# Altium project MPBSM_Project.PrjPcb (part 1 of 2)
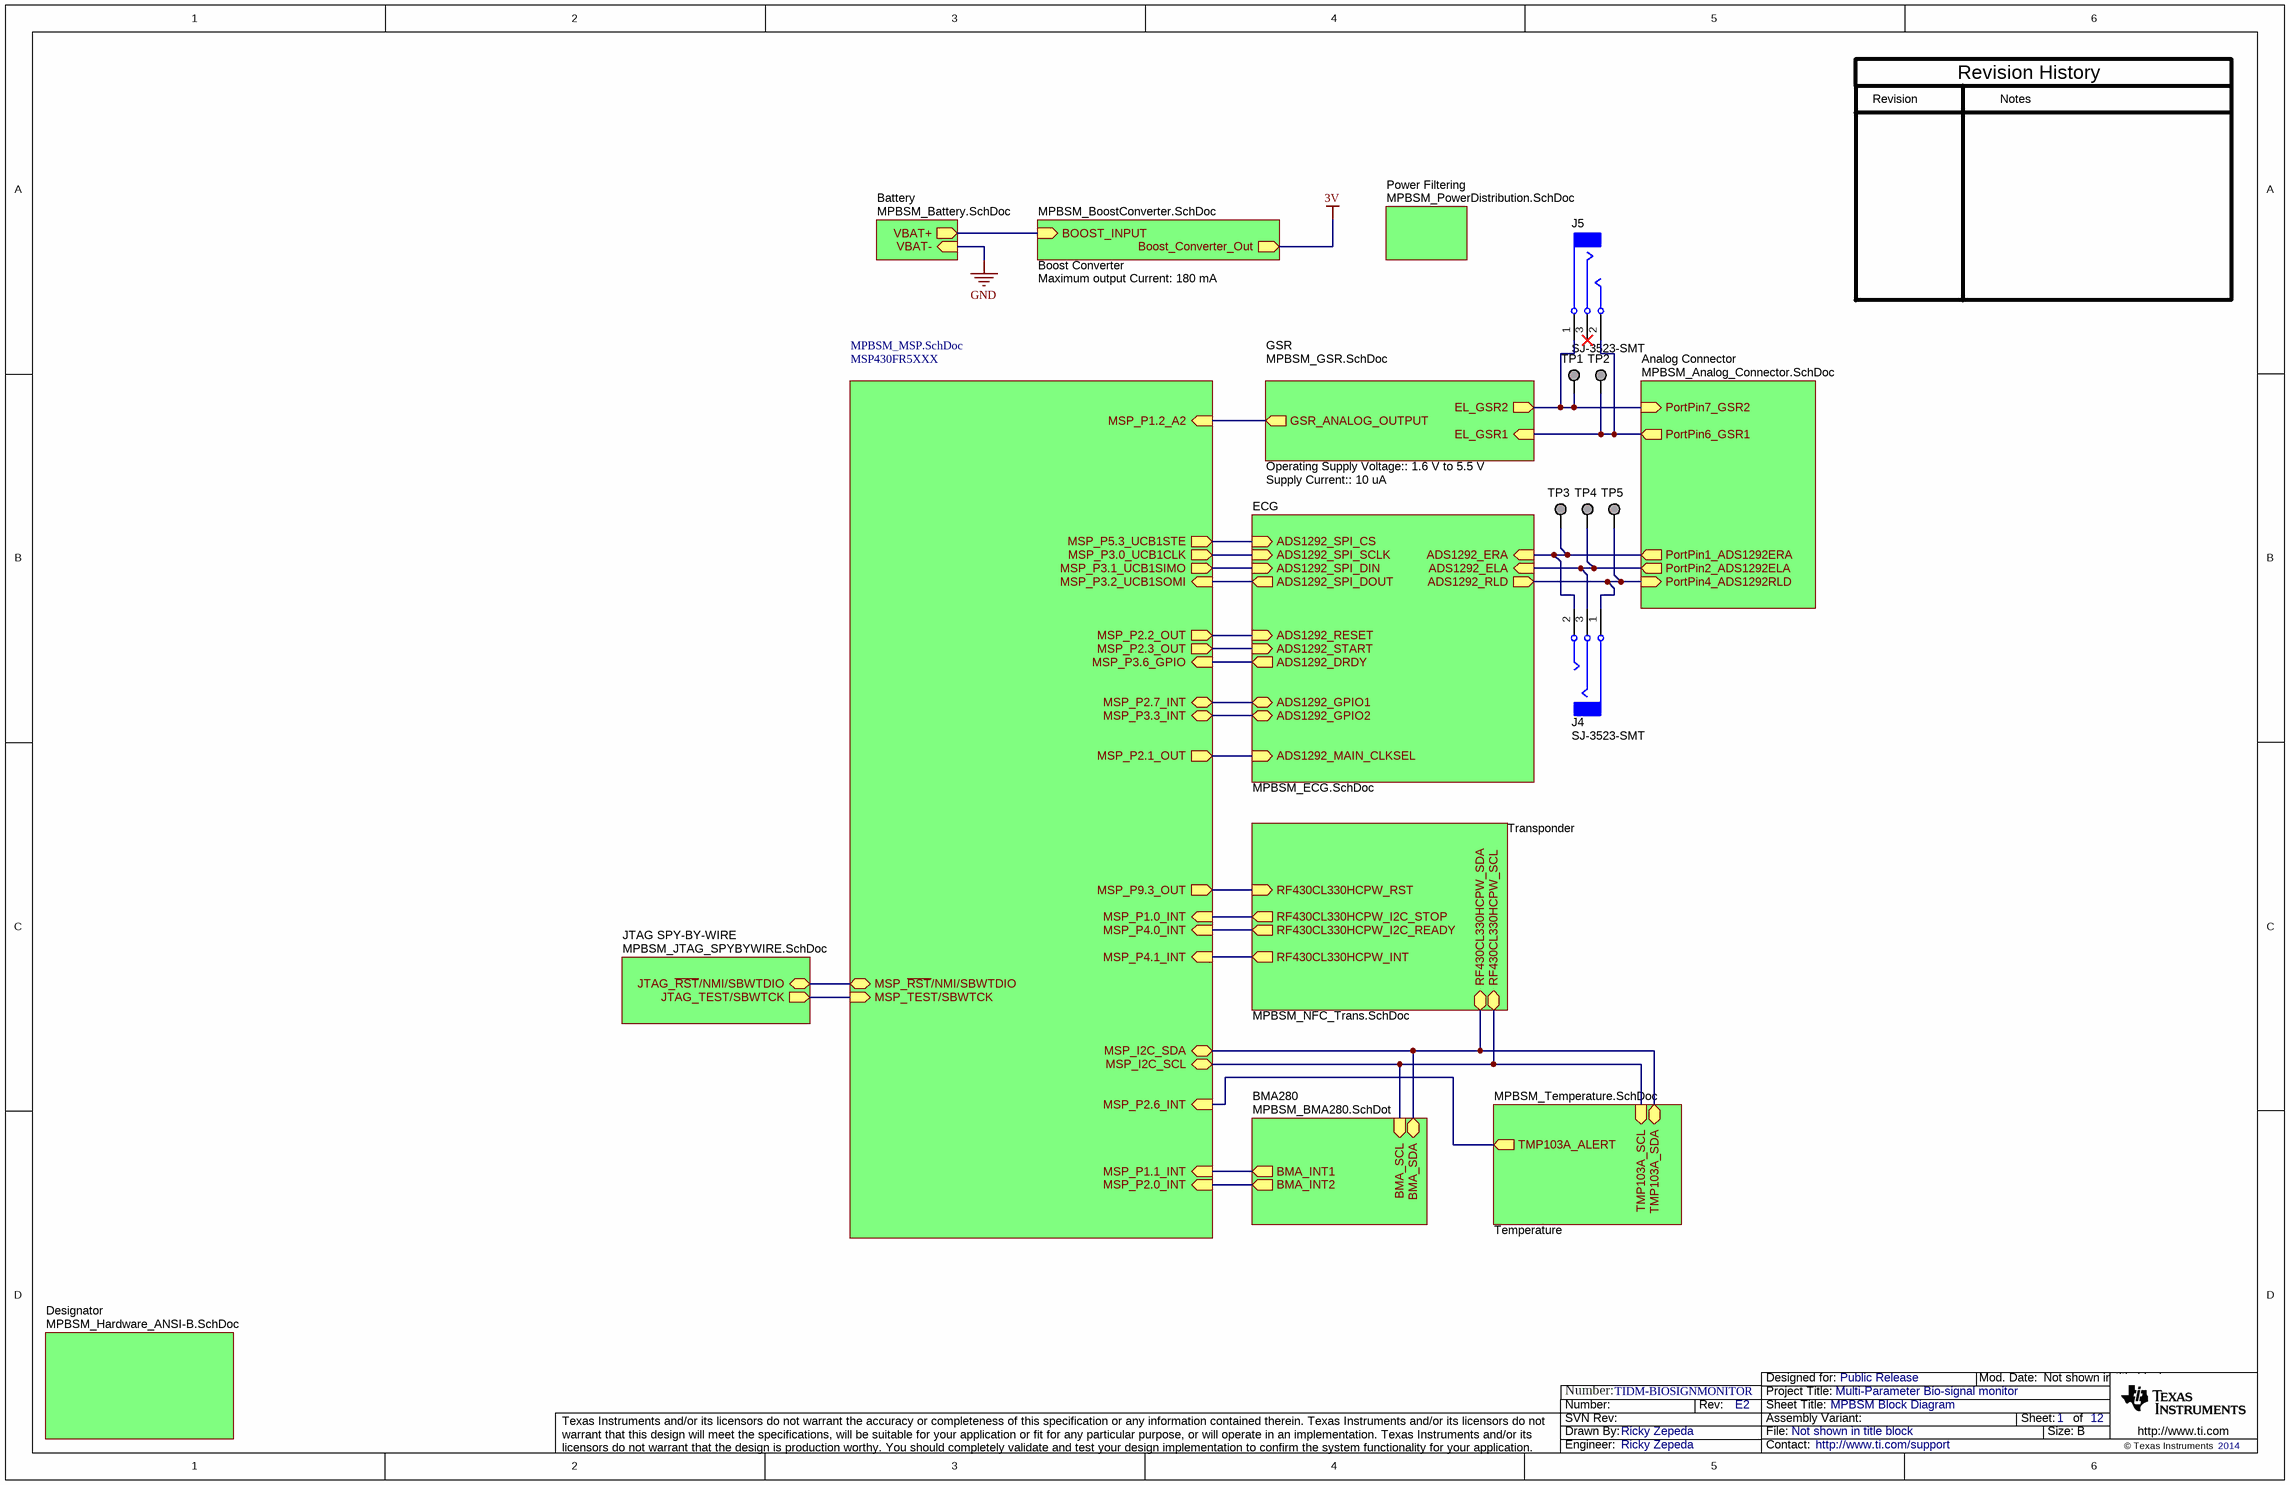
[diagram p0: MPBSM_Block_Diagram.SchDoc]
CopyrightYear: 2014; PCB_Layout: Ricardo Zepeda; PCB_Rev: 002; PRJ_Customer: Public Release; PRJ_Engineer: Ricky Zepeda; PRJ_Title: Multi-Parameter Bio-signal monitor; SCH_Rev: E2; TechSupport: http://www.ti.com/support
12 sheets, 158 parts. Net scope: hierarchical (ports join the sheet entries above them; power ports are global).
Board files: MPBSMLayoutvOverlay.PcbDoc, MPBSMLayoutvFR4.PcbDoc
Sheets:
  MPBSM_Block_Diagram.SchDoc
    MSP430FR5XXX = MPBSM_MSP.SchDoc
    Designator = MPBSM_Hardware_ANSI-B.SchDoc
    JTAG SPY-BY-WIRE = MPBSM_JTAG_SPYBYWIRE.SchDoc
    GSR = MPBSM_GSR.SchDoc
    Battery = MPBSM_Battery.SchDoc
    Boost Converter = MPBSM_BoostConverter.SchDoc
    Transponder = MPBSM_NFC_Trans.SchDoc
    Temperature = MPBSM_Temperature.SchDoc
    ECG = MPBSM_ECG.SchDoc
    Power Filtering = MPBSM_PowerDistribution.SchDoc
    Analog Connector = MPBSM_Analog_Connector.SchDoc

## Sheet MPBSM_Block_Diagram.SchDoc: MPBSM Block Diagram
size 431 x 279 mm; Date: Not shown in title block; ApprovedBy: Not shown in title block; CheckedBy: Not shown in title block; Author: Not shown in title block; CompanyName: Not shown in title block; DrawnBy: Ricky Zepeda; Engineer: Not shown in title block; Organization: Not shown in title block; Address1: Not shown in title block; Address2: Not shown in title block; Address3: Not shown in title block; Address4: Not shown in title block; DocumentNumber: 1; Revision: Use project parameter SCH_Rev; SheetNumber: 1; SheetTotal: 12; PageSetup: Record=PageOptions¦CenterHorizontal=True¦CenterVertical=True¦PrintScale=1.00¦XCorrection=1.00¦YCorrection=1.00¦PrintKind=0¦BorderSize=5000000¦LeftOffset=0¦BottomOffset=0¦Orientation=2¦PaperLength=1000¦PaperWidth=1000¦Scale=100¦PaperSource=15¦PrintQuality=600¦MediaType=1¦DitherType=10¦PaperKind=Letter¦PrintScaleMode=1

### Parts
J4  SJ-3523-SMT  [CUI_SJ-3523-SMT]
J5  SJ-3523-SMT  [CUI_SJ-3523-SMT]
TP1  TESTPOINT  [TP_SM_1MM]  (value not drawn)  (no BOM)
TP2  TESTPOINT  [TP_SM_1MM]  (value not drawn)  (no BOM)
TP3  TESTPOINT  [TP_SM_1MM]  (value not drawn)  (no BOM)
TP4  TESTPOINT  [TP_SM_1MM]  (value not drawn)  (no BOM)
TP5  TESTPOINT  [TP_SM_1MM]  (value not drawn)  (no BOM)

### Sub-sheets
Analog Connector = MPBSM_Analog_Connector.SchDoc: PortPin7_GSR2 (in), PortPin6_GSR1 (out), PortPin2_ADS1292ELA (out), PortPin4_ADS1292RLD (in), PortPin1_ADS1292ERA (out)
Battery = MPBSM_Battery.SchDoc: VBAT- (in), VBAT+ (out)
BMA280 = MPBSM_BMA280.SchDot (file not in this document): BMA_INT1 (out), BMA_INT2 (out), BMA_SDA (bidir), BMA_SCL (in)
Boost Converter = MPBSM_BoostConverter.SchDoc: BOOST_INPUT (in), Boost_Converter_Out (out)  | Maximum output Current: 180 mA
Designator = MPBSM_Hardware_ANSI-B.SchDoc: no entries
ECG = MPBSM_ECG.SchDoc: ADS1292_START (in), ADS1292_RESET (in), ADS1292_DRDY (out), ADS1292_SPI_CS (in), ADS1292_SPI_DIN (in), ADS1292_SPI_SCLK (in), ADS1292_SPI_DOUT (out), ADS1292_MAIN_CLKSEL (in), ADS1292_ERA (in), ADS1292_ELA (in), ADS1292_GPIO1 (bidir), ADS1292_GPIO2 (bidir), ADS1292_RLD (out)
GSR = MPBSM_GSR.SchDoc: GSR_ANALOG_OUTPUT (out), EL_GSR2 (out), EL_GSR1 (in)  | Operating Supply Voltage:: 1.6 V to 5.5 V; Supply Current:: 10 uA
JTAG SPY-BY-WIRE = MPBSM_JTAG_SPYBYWIRE.SchDoc: JTAG_~{RST}/NMI/SBWTDIO (bidir), JTAG_TEST/SBWTCK (out)
MSP430FR5XXX = MPBSM_MSP.SchDoc: MSP_TEST/SBWTCK (in), MSP_~{RST}/NMI/SBWTDIO (bidir), MSP_I2C_SDA (bidir), MSP_I2C_SCL (bidir), MSP_P1.2_A2 (in), MSP_P2.0_INT (in), MSP_P4.0_INT (in), MSP_P4.1_INT (in), MSP_P2.7_INT (bidir), MSP_P9.3_OUT (out), MSP_P2.2_OUT (out), MSP_P2.3_OUT (out), MSP_P1.0_INT (in), MSP_P2.1_OUT (out), MSP_P3.0_UCB1CLK (out), MSP_P3.3_INT (bidir), MSP_P3.2_UCB1SOMI (in), MSP_P3.6_GPIO (in), MSP_P1.1_INT (in), MSP_P5.3_UCB1STE (out), MSP_P3.1_UCB1SIMO (out), MSP_P2.6_INT (in)
Power Filtering = MPBSM_PowerDistribution.SchDoc: no entries
Temperature = MPBSM_Temperature.SchDoc: TMP103A_SCL (in), TMP103A_SDA (bidir), TMP103A_ALERT (out)
Transponder = MPBSM_NFC_Trans.SchDoc: RF430CL330HCPW_RST (in), RF430CL330HCPW_SCL (bidir), RF430CL330HCPW_SDA (bidir), RF430CL330HCPW_I2C_STOP (out), RF430CL330HCPW_I2C_READY (out), RF430CL330HCPW_INT (out)

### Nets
ADS1292_DRDY: sheet MSP430FR5XXX/MSP_P3.6_GPIO, sheet ECG/ADS1292_DRDY
ADS1292_ELA: J4.3(RING) TP4.1 ; sheet ECG/ADS1292_ELA, sheet Analog Connector/PortPin2_ADS1292ELA
ADS1292_ERA: J4.2(TIP) TP3.1 ; sheet ECG/ADS1292_ERA, sheet Analog Connector/PortPin1_ADS1292ERA
ADS1292_GPIO1: sheet MSP430FR5XXX/MSP_P2.7_INT, sheet ECG/ADS1292_GPIO1
ADS1292_GPIO2: sheet MSP430FR5XXX/MSP_P3.3_INT, sheet ECG/ADS1292_GPIO2
ADS1292_MAIN_CLKSEL: sheet MSP430FR5XXX/MSP_P2.1_OUT, sheet ECG/ADS1292_MAIN_CLKSEL
ADS1292_RESET: sheet MSP430FR5XXX/MSP_P2.2_OUT, sheet ECG/ADS1292_RESET
ADS1292_RLD: J4.1(SLEEVE) TP5.1 ; sheet ECG/ADS1292_RLD, sheet Analog Connector/PortPin4_ADS1292RLD
ADS1292_SPI_CS: sheet MSP430FR5XXX/MSP_P5.3_UCB1STE, sheet ECG/ADS1292_SPI_CS
ADS1292_SPI_DIN: sheet MSP430FR5XXX/MSP_P3.1_UCB1SIMO, sheet ECG/ADS1292_SPI_DIN
ADS1292_SPI_DOUT: sheet MSP430FR5XXX/MSP_P3.2_UCB1SOMI, sheet ECG/ADS1292_SPI_DOUT
ADS1292_SPI_SCLK: sheet MSP430FR5XXX/MSP_P3.0_UCB1CLK, sheet ECG/ADS1292_SPI_SCLK
ADS1292_START: sheet MSP430FR5XXX/MSP_P2.3_OUT, sheet ECG/ADS1292_START
BOOST_INPUT: sheet Battery/VBAT+, sheet Boost Converter/BOOST_INPUT
EL_GSR1: J5.2(TIP) TP2.1 ; sheet GSR/EL_GSR1, sheet Analog Connector/PortPin6_GSR1
EL_GSR2: J5.1(SLEEVE) TP1.1 ; sheet GSR/EL_GSR2, sheet Analog Connector/PortPin7_GSR2
GSR_ANALOG_OUTPUT: sheet MSP430FR5XXX/MSP_P1.2_A2, sheet GSR/GSR_ANALOG_OUTPUT
JTAG_TDO/TDI: sheet MSP430FR5XXX/MSP_~{RST}/NMI/SBWTDIO, sheet JTAG SPY-BY-WIRE/JTAG_~{RST}/NMI/SBWTDIO
JTAG_TEST/SBWTCK: sheet MSP430FR5XXX/MSP_TEST/SBWTCK, sheet JTAG SPY-BY-WIRE/JTAG_TEST/SBWTCK
MSP_P1.0_INT: sheet MSP430FR5XXX/MSP_P1.0_INT, sheet Transponder/RF430CL330HCPW_I2C_STOP
MSP_P1.1_INT: sheet MSP430FR5XXX/MSP_P1.1_INT, sheet BMA280/BMA_INT1
MSP_P2.0_INT: sheet MSP430FR5XXX/MSP_P2.0_INT, sheet BMA280/BMA_INT2
MSP_P2.6_INT: sheet MSP430FR5XXX/MSP_P2.6_INT, sheet Temperature/TMP103A_ALERT
MSP_P4.0_INT: sheet MSP430FR5XXX/MSP_P4.0_INT, sheet Transponder/RF430CL330HCPW_I2C_READY
MSP_P4.1_INT: sheet MSP430FR5XXX/MSP_P4.1_INT, sheet Transponder/RF430CL330HCPW_INT
MSP_P9.3_OUT: sheet MSP430FR5XXX/MSP_P9.3_OUT, sheet Transponder/RF430CL330HCPW_RST
MSP_UCB0SCL_TMP103_SCL_RF430CL330HCPW_SCL: sheet MSP430FR5XXX/MSP_I2C_SCL, sheet Transponder/RF430CL330HCPW_SCL, sheet BMA280/BMA_SCL, sheet Temperature/TMP103A_SCL
MSP_UCB0SDA_TMP103_SDA_RF430CL330HCPW_SDA: sheet MSP430FR5XXX/MSP_I2C_SDA, sheet Transponder/RF430CL330HCPW_SDA, sheet BMA280/BMA_SDA, sheet Temperature/TMP103A_SDA

Not connected (* = marked no-connect by the designer): J5 3(RING)*

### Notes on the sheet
- Revision
- Notes
- Revision History
- Number:
- TIDM-BIOSIGNMONITOR

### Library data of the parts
J4 J5 = SJ-3523-SMT: Audio Jack, 3.5mm, Stereo, R/A, SMT; Manufacturer: CUI Inc.; SymbolCreator: a0412235
TP1-TP5 = TP_SM_1MM: 1mm Test Point, SMT; Manufacturer: Any

## Sheet MPBSM_MSP.SchDoc: MPBSM MSP4305889 MCU
size 431 x 279 mm; Date: Not shown in title block; ApprovedBy: Not shown in title block; CheckedBy: Not shown in title block; Author: Not shown in title block; CompanyName: Not shown in title block; Engineer: Not shown in title block; Organization: Not shown in title block; Address1: Not shown in title block; Address2: Not shown in title block; Address3: Not shown in title block; Address4: Not shown in title block; DocumentNumber: 6; Revision: Use project parameter SCH_Rev; SheetNumber: 6; SheetTotal: 12; PageSetup: Record=PageOptions¦CenterHorizontal=True¦CenterVertical=True¦PrintScale=0.62¦XCorrection=1.00¦YCorrection=1.00¦PrintKind=0¦BorderSize=5000000¦LeftOffset=0¦BottomOffset=0¦Orientation=2¦PaperLength=1000¦PaperWidth=1000¦Scale=100¦PaperSource=15¦PrintQuality=600¦MediaType=1¦DitherType=10¦PaperKind=Letter¦PrintScaleMode=1
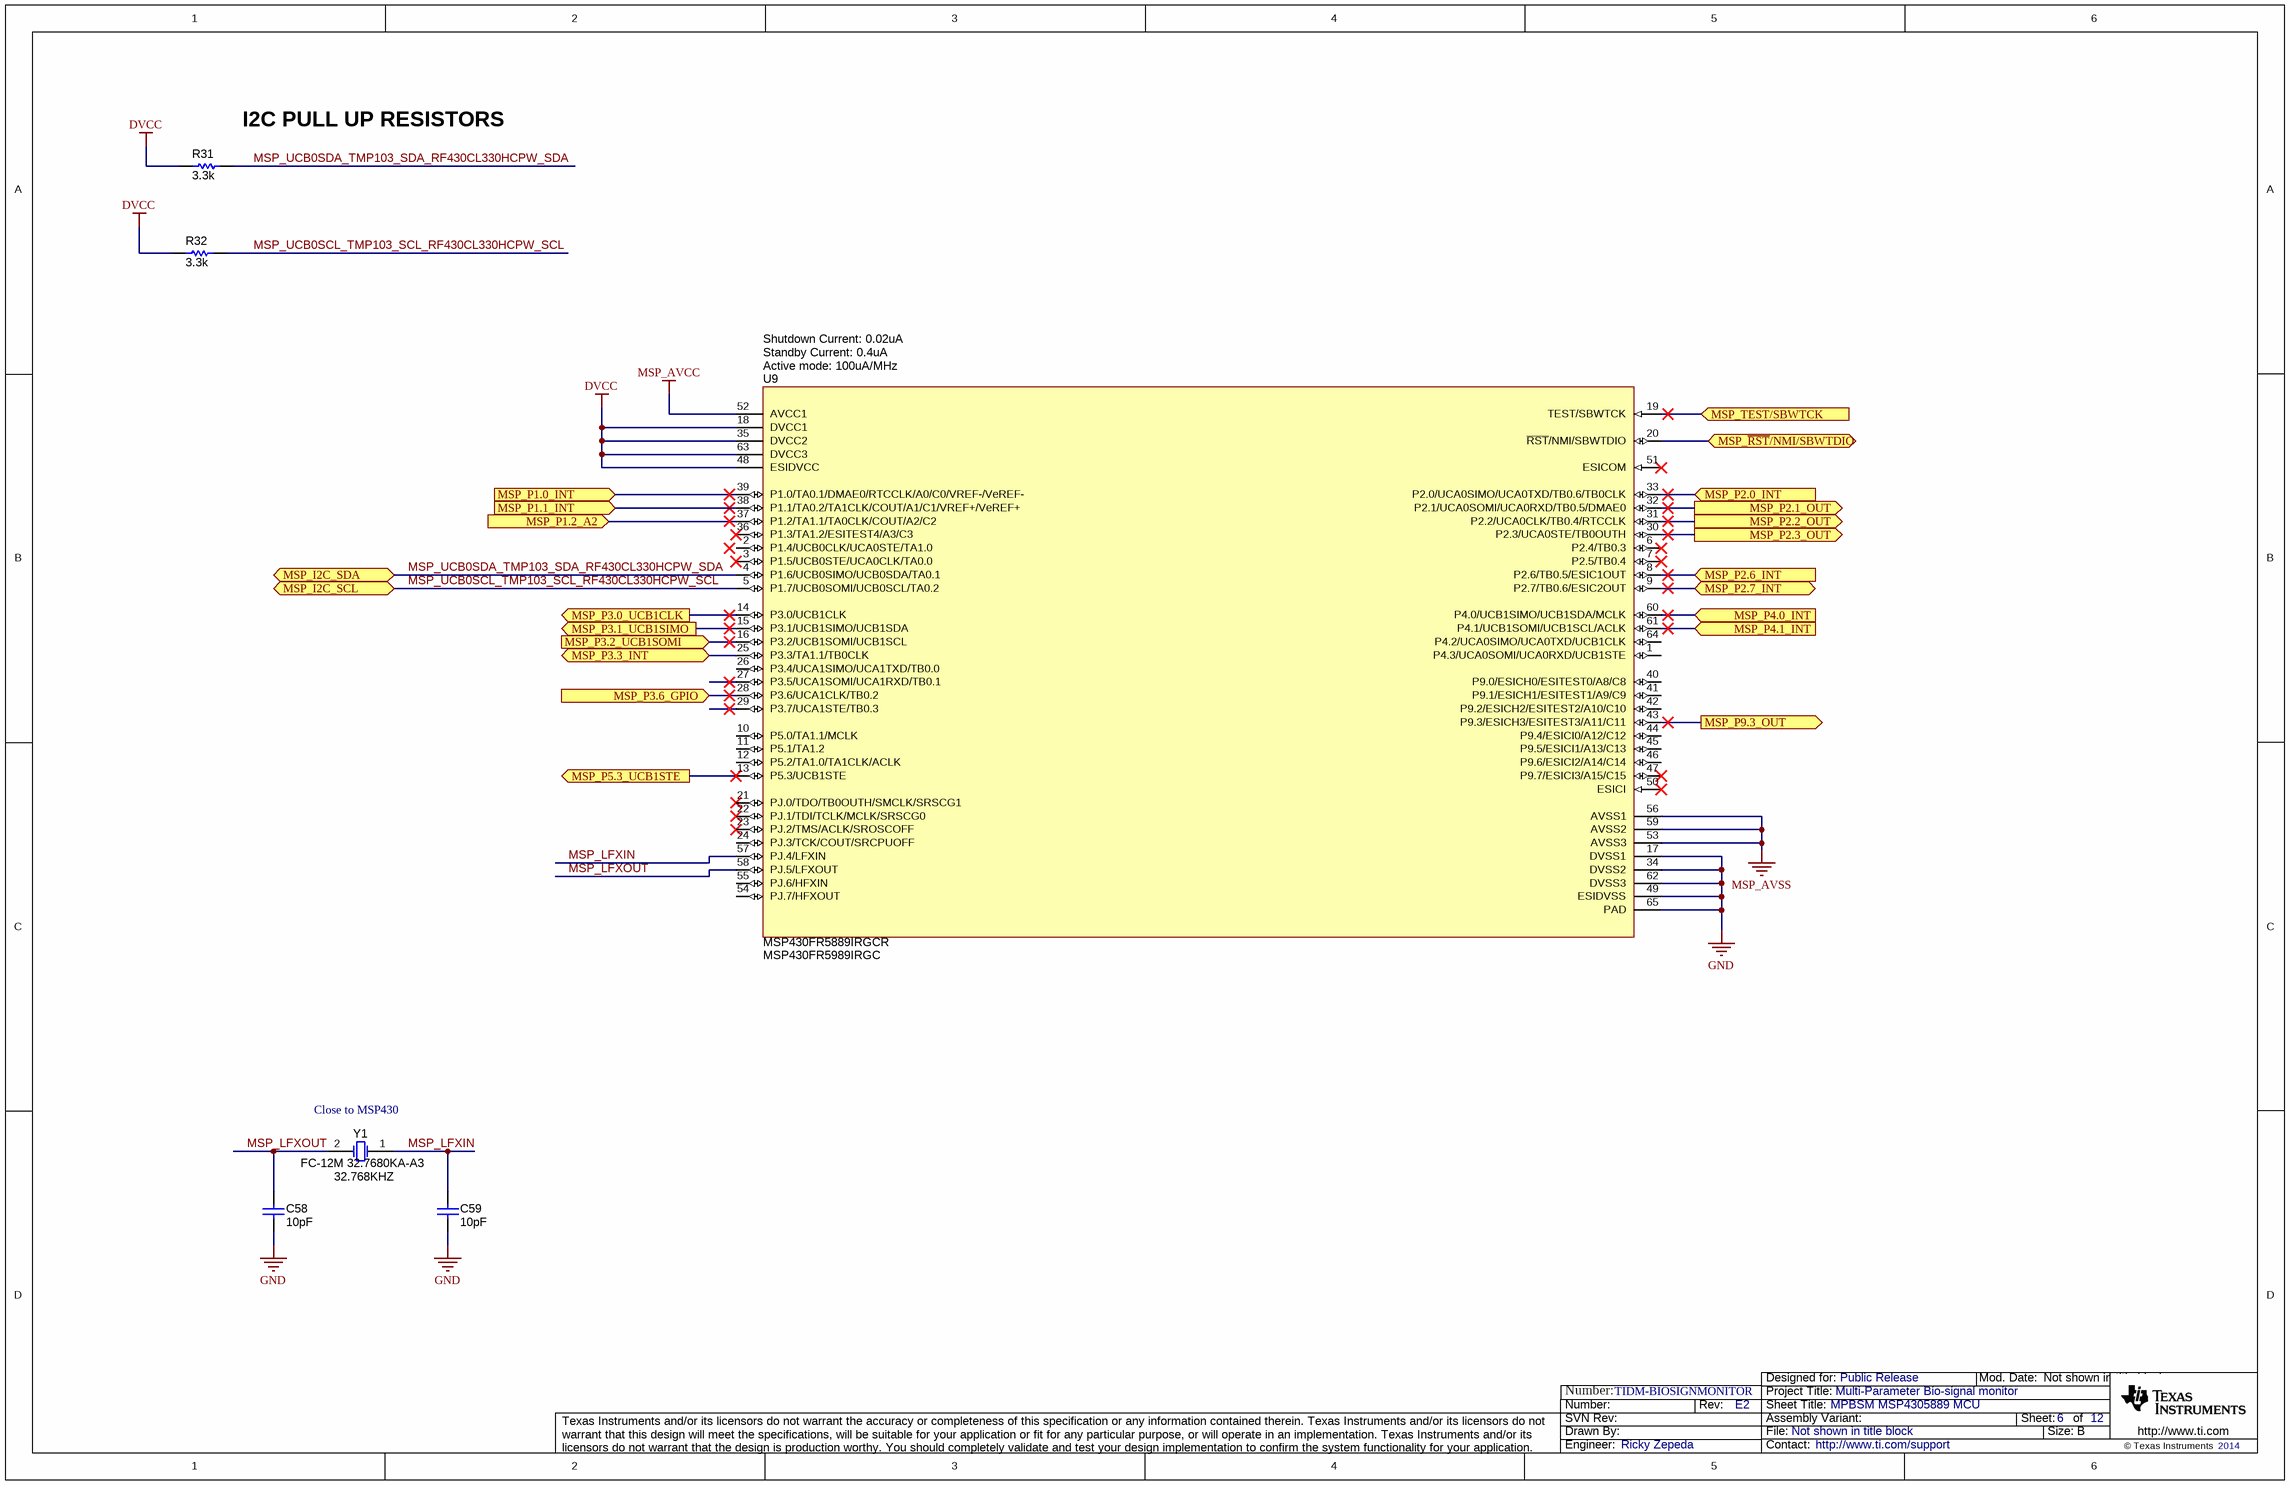
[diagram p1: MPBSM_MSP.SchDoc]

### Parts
C58  ValueDisplayed: 10pF  [0603]  (hidden comment: 06035A100JAT2A)
C59  ValueDisplayed: 10pF  [0603]  (hidden comment: 06035A100JAT2A)
R31  ValueDisplayed: 3.3k  [0402]  (hidden comment: CRCW04023K30JNED)
R32  ValueDisplayed: 3.3k  [0402]  (hidden comment: CRCW04023K30JNED)
U9  MSP430FR5889IRGCR  Alternate PartNumber: MSP430FR5989IRGC  Active mode: 100uA/MHz  Standby Current: 0.4uA  Shutdown Current: 0.02uA  [RGC0064B]
Y1  FC-12M 32.7680KA-A3  Frequency: 32.768KHZ  [Epson_FC-12M]

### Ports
MSP_I2C_SCL (bidir), MSP_I2C_SDA (bidir), MSP_P1.0_INT (in), MSP_P1.1_INT (in), MSP_P1.2_A2 (in), MSP_P2.0_INT (in), MSP_P2.1_OUT (out), MSP_P2.2_OUT (out), MSP_P2.3_OUT (out), MSP_P2.6_INT (in), MSP_P2.7_INT (bidir), MSP_P3.0_UCB1CLK (out), MSP_P3.1_UCB1SIMO (out), MSP_P3.2_UCB1SOMI (in), MSP_P3.3_INT (bidir), MSP_P3.6_GPIO (in), MSP_P4.0_INT (in), MSP_P4.1_INT (in), MSP_P5.3_UCB1STE (out), MSP_P9.3_OUT (out), MSP_TEST/SBWTCK (in), MSP_~{RST}/NMI/SBWTDIO (bidir)

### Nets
DVCC: R31.1 R32.1 U9.18(DVCC1) U9.35(DVCC2) U9.48(ESIDVCC) U9.63(DVCC3)
GND: C58.2 C59.2 U9.17(DVSS1) U9.34(DVSS2) U9.49(ESIDVSS) U9.62(DVSS3) U9.65(PAD)
MSP_AVCC: U9.52(AVCC1)
MSP_AVSS: U9.53(AVSS3) U9.56(AVSS1) U9.59(AVSS2)
ADS1292_DRDY: U9.28(P3.6/UCA1CLK/TB0.2) ; port MSP_P3.6_GPIO
ADS1292_GPIO1: U9.9(P2.7/TB0.6/ESIC2OUT) ; port MSP_P2.7_INT
ADS1292_GPIO2: U9.25(P3.3/TA1.1/TB0CLK) ; port MSP_P3.3_INT
ADS1292_MAIN_CLKSEL: U9.32(P2.1/UCA0SOMI/UCA0RXD/TB0.5/DMAE0) ; port MSP_P2.1_OUT
ADS1292_RESET: U9.31(P2.2/UCA0CLK/TB0.4/RTCCLK) ; port MSP_P2.2_OUT
ADS1292_SPI_CS: U9.13(P5.3/UCB1STE) ; port MSP_P5.3_UCB1STE
ADS1292_SPI_DIN: U9.15(P3.1/UCB1SIMO/UCB1SDA) ; port MSP_P3.1_UCB1SIMO
ADS1292_SPI_DOUT: U9.16(P3.2/UCB1SOMI/UCB1SCL) ; port MSP_P3.2_UCB1SOMI
ADS1292_SPI_SCLK: U9.14(P3.0/UCB1CLK) ; port MSP_P3.0_UCB1CLK
ADS1292_START: U9.30(P2.3/UCA0STE/TB0OUTH) ; port MSP_P2.3_OUT
GSR_ANALOG_OUTPUT: U9.37(P1.2/TA1.1/TA0CLK/COUT/A2/C2) ; port MSP_P1.2_A2
JTAG_TDO/TDI: U9.20(~{RST}/NMI/SBWTDIO) ; port MSP_~{RST}/NMI/SBWTDIO
JTAG_TEST/SBWTCK: U9.19(TEST/SBWTCK) ; port MSP_TEST/SBWTCK
MSP_LFXIN: C59.1 U9.57(PJ.4/LFXIN) Y1.1(OSC1)
MSP_LFXOUT: C58.1 U9.58(PJ.5/LFXOUT) Y1.2(OSC2)
MSP_P1.0_INT: U9.39(P1.0/TA0.1/DMAE0/RTCCLK/A0/C0/VREF-/VeREF-) ; port MSP_P1.0_INT
MSP_P1.1_INT: U9.38(P1.1/TA0.2/TA1CLK/COUT/A1/C1/VREF+/VeREF+) ; port MSP_P1.1_INT
MSP_P2.0_INT: U9.33(P2.0/UCA0SIMO/UCA0TXD/TB0.6/TB0CLK) ; port MSP_P2.0_INT
MSP_P2.6_INT: U9.8(P2.6/TB0.5/ESIC1OUT) ; port MSP_P2.6_INT
MSP_P4.0_INT: U9.60(P4.0/UCB1SIMO/UCB1SDA/MCLK) ; port MSP_P4.0_INT
MSP_P4.1_INT: U9.61(P4.1/UCB1SOMI/UCB1SCL/ACLK) ; port MSP_P4.1_INT
MSP_P9.3_OUT: U9.43(P9.3/ESICH3/ESITEST3/A11/C11) ; port MSP_P9.3_OUT
MSP_UCB0SCL_TMP103_SCL_RF430CL330HCPW_SCL: R32.2 U9.5(P1.7/UCB0SOMI/UCB0SCL/TA0.2) ; port MSP_I2C_SCL
MSP_UCB0SDA_TMP103_SDA_RF430CL330HCPW_SDA: R31.2 U9.4(P1.6/UCB0SIMO/UCB0SDA/TA0.1) ; port MSP_I2C_SDA

Not connected (* = marked no-connect by the designer): U9 1(P4.3/UCA0SOMI/UCA0RXD/UCB1STE) 2(P1.4/UCB0CLK/UCA0STE/TA1.0) 3(P1.5/UCB0STE/UCA0CLK/TA0.0)* 6(P2.4/TB0.3)* 7(P2.5/TB0.4)* 10(P5.0/TA1.1/MCLK) 11(P5.1/TA1.2) 12(P5.2/TA1.0/TA1CLK/ACLK) 21(PJ.0/TDO/TB0OUTH/SMCLK/SRSCG1)* 22(PJ.1/TDI/TCLK/MCLK/SRSCG0)* 23(PJ.2/TMS/ACLK/SROSCOFF)* 24(PJ.3/TCK/COUT/SRCPUOFF) 26(P3.4/UCA1SIMO/UCA1TXD/TB0.0) 27(P3.5/UCA1SOMI/UCA1RXD/TB0.1)* 29(P3.7/UCA1STE/TB0.3)* 36(P1.3/TA1.2/ESITEST4/A3/C3)* 40(P9.0/ESICH0/ESITEST0/A8/C8) 41(P9.1/ESICH1/ESITEST1/A9/C9) 42(P9.2/ESICH2/ESITEST2/A10/C10) 44(P9.4/ESICI0/A12/C12) 45(P9.5/ESICI1/A13/C13) 46(P9.6/ESICI2/A14/C14) 47(P9.7/ESICI3/A15/C15)* 50(ESICI)* 51(ESICOM)* 54(PJ.7/HFXOUT) 55(PJ.6/HFXIN) 64(P4.2/UCA0SIMO/UCA0TXD/UCB1CLK)

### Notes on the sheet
- (near R31) I2C PULL UP RESISTORS
- (near Y1) Close to MSP430
- Number:
- TIDM-BIOSIGNMONITOR

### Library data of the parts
C58 C59 = 06035A100JAT2A: CAP, CERM, 10 pF, 50 V, +/- 5%, C0G/NP0, 0603; Manufacturer: AVX; Polarized: N; CompType: Capacitor; Value: 10pF; U/M: EA; Cap_F: 0.00000000001; Tolerance_%: 5; ESR_ohm: 0.403; Value1: 0.403 ohm; VDC_V: 50; Value2: 50V; TaMin_C: -55; TaMax_C: 125
R31 R32 = CRCW04023K30JNED: RES, 3.3 k, 5%, 0.063 W, 0402; Manufacturer: Vishay-Dale; CompType: Resistor; Value: 3.3k; Res_ohm: 3300; Value_Code: 3k30; Tolerance_%: 5; Power_W: 0.063; Value2: 0.063W; VDC_V: 50; TempCo: 200 ppm/C; EIA_Code: E24; U/M: EA
U9 = MSP430FR5889IRGCR: Mixed-Signal Microcontrollers, RGC0064B; Alternate Manufacturer: Texas Instruments; SymbolCreator: Altium; CompType: IC; U/M: EA; SupplyVoltage: 1.8 V to 3.6 V; SupplyVoltageMax_V: 3.6 V; SupplyVoltageMin_V: 1.8 V; TaMax_C: -40 °C; TaMin_C: +125 °C
Y1 = FC-12M 32.7680KA-A3: Crystal, 32.768kHz, 12.5pF, SMD; Manufacturer: Epson; SymbolCreator: a0412235; U/M: EA; TaMin_C: -40 °C; TaMax_C: 85 °C; Value2: 90 kOhm; Value3: ±20ppm

## Sheet MPBSM_Hardware_ANSI-B.SchDoc: MPBSM Assembly Document
size 431 x 279 mm; Date: Not shown in title block; ApprovedBy: Not shown in title block; CheckedBy: Not shown in title block; Author: Not shown in title block; CompanyName: Not shown in title block; Engineer: Not shown in title block; Organization: Not shown in title block; Address1: Not shown in title block; Address2: Not shown in title block; Address3: Not shown in title block; Address4: Not shown in title block; DocumentNumber: 12; Revision: Use project parameter SCH_Rev; SheetNumber: 12; SheetTotal: 12; PageSetup: Record=PageOptions¦CenterHorizontal=True¦CenterVertical=True¦PrintScale=1.00¦XCorrection=1.00¦YCorrection=1.00¦PrintKind=0¦BorderSize=5000000¦LeftOffset=0¦BottomOffset=0¦Orientation=2¦PaperLength=1000¦PaperWidth=1000¦Scale=100¦PaperSource=15¦PrintQuality=600¦MediaType=1¦DitherType=10¦PaperKind=Letter¦PrintScaleMode=1
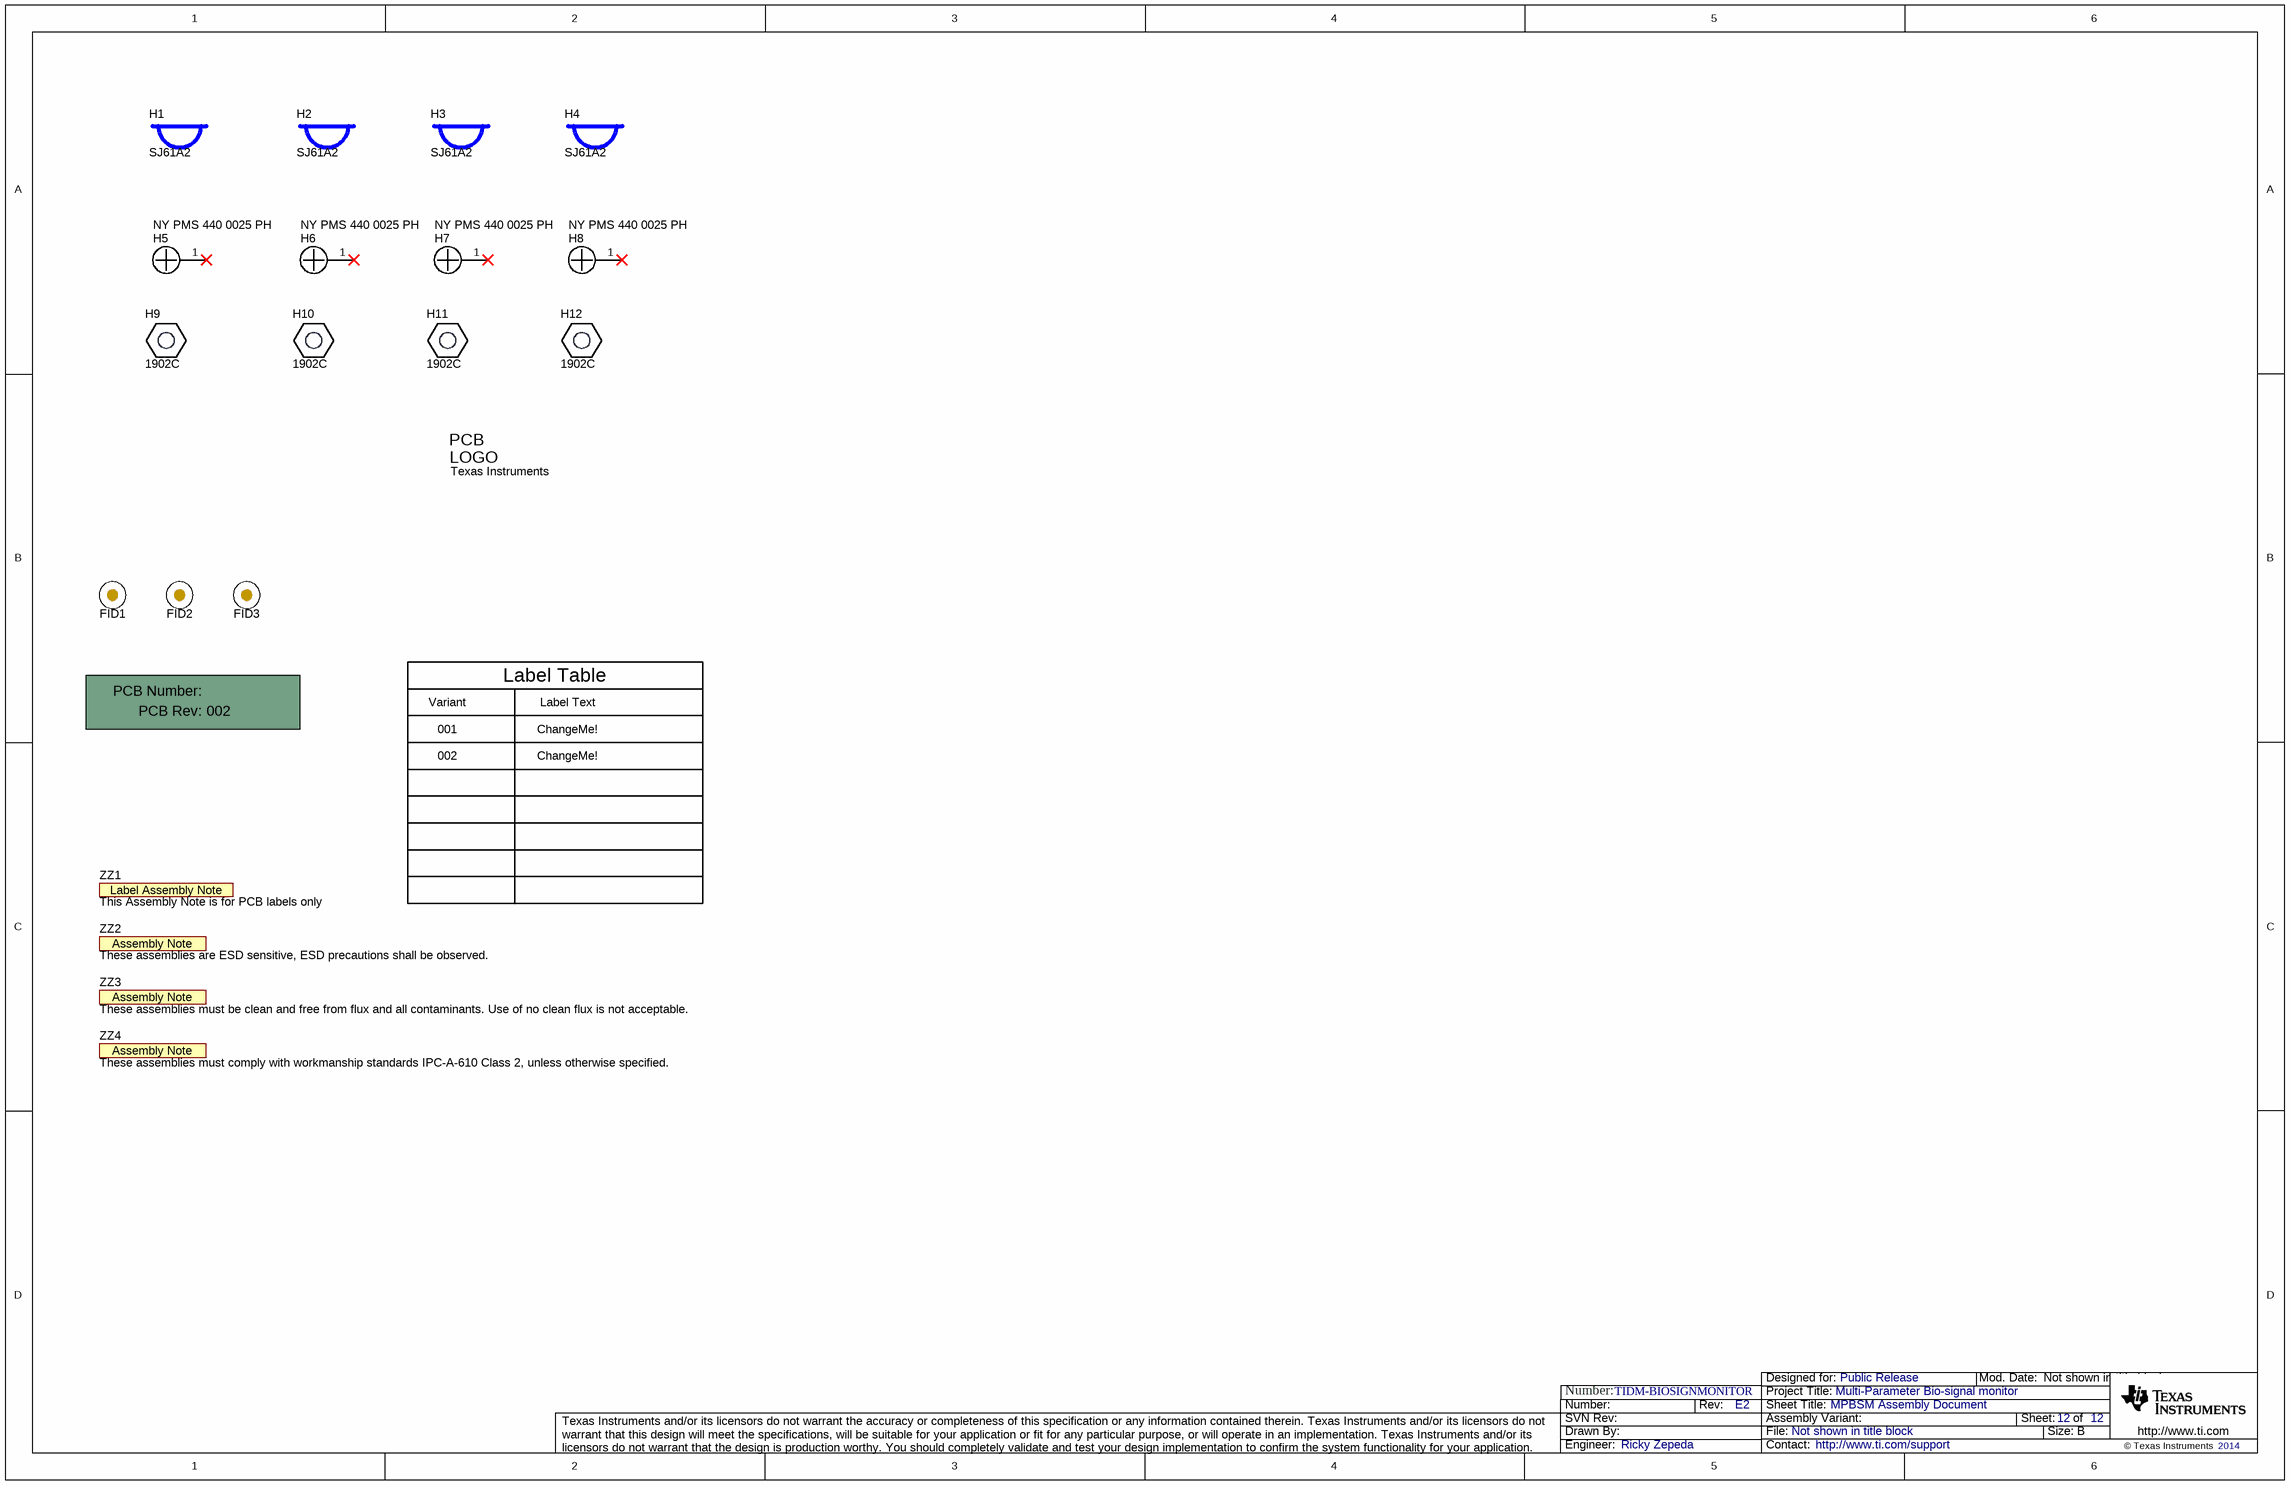
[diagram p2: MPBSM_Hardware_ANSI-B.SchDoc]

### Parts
!PCB1  Printed Circuit Board  (value not drawn)  (mechanical)
FID1  Fiducial  [Fiducial10-20]  (value not drawn)
FID2  Fiducial  [Fiducial10-20]  (value not drawn)
FID3  Fiducial  [Fiducial10-20]  (value not drawn)
H1  SJ61A2  [Bumpon_SJ61A2]
H2  SJ61A2  [Bumpon_SJ61A2]
H3  SJ61A2  [Bumpon_SJ61A2]
H4  SJ61A2  [Bumpon_SJ61A2]
H5  NY PMS 440 0025 PH  [NY PMS 440 0025 PH]
H6  NY PMS 440 0025 PH  [NY PMS 440 0025 PH]
H7  NY PMS 440 0025 PH  [NY PMS 440 0025 PH]
H8  NY PMS 440 0025 PH  [NY PMS 440 0025 PH]
H9  1902C  [Keystone_1902C]
H10  1902C  [Keystone_1902C]
H11  1902C  [Keystone_1902C]
H12  1902C  [Keystone_1902C]
Logo1  Texas Instruments  [TI_Symbol_Overlay_Small]  (no BOM)
ZZ1  This Assembly Note is for PCB labels only  [AssemblyNoteLabel]  (no BOM)
ZZ2  These assemblies are ESD sensitive, ESD precautions shall be observed.  [AssemblyNote]  (no BOM)
ZZ3  These assemblies must be clean and free from flux and all contaminants. Use of no clean flux is not acceptable.  [AssemblyNote]  (no BOM)
ZZ4  These assemblies must comply with workmanship standards IPC-A-610 Class 2, unless otherwise specified.  [AssemblyNote]  (no BOM)

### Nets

Not connected (* = marked no-connect by the designer): H5 1*; H6 1*; H7 1*; H8 1*

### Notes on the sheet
- Variant
- Label Table
- Label Text
- 001
- 002
- ChangeMe!
- Number:
- TIDM-BIOSIGNMONITOR

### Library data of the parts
!PCB1 = PCB: Manufacturer: Any; SymbolCreator: a0412235
FID1-FID3 = Fiducial: Fiducial mark.  There is nothing to buy or mount.; SymbolCreator: codlsc
H1-H4 = SJ61A2: Bumpon, Hemisphere, 0.375 X 0.235, Black; Manufacturer: 3M; SymbolCreator: a0412235
H5-H8 = NY PMS 440 0025 PH: Machine Screw, Round, #4-40 x 1/4, Nylon, Philips panhead; Manufacturer: B&F Fastener Supply; CompType: Hardware; SymbolCreator: codlsc; U/M: EA
H9-H12 = 1902C: Standoff, Hex, 0.5"L #4-40 Nylon; Manufacturer: Keystone; CompType: Hardware
Logo1 = TI_Logo: Texas Instrument Corporate Signature; SymbolCreator: codlsc
ZZ1 = AssemblyNoteLabel: SymbolCreator: a0412235
ZZ2-ZZ4 = AssemblyNote: SymbolCreator: codlsc

## Sheet MPBSM_JTAG_SPYBYWIRE.SchDoc: JTAG SPY-BY-WIRE Subcircuit
size 431 x 279 mm; Date: Not shown in title block; ApprovedBy: Not shown in title block; CheckedBy: Not shown in title block; Author: Not shown in title block; CompanyName: Not shown in title block; Engineer: Not shown in title block; Organization: Not shown in title block; Address1: Not shown in title block; Address2: Not shown in title block; Address3: Not shown in title block; Address4: Not shown in title block; DocumentNumber: 5; Revision: Use project parameter SCH_Rev; SheetNumber: 5; SheetTotal: 12; PageSetup: Record=PageOptions¦CenterHorizontal=True¦CenterVertical=True¦PrintScale=0.62¦XCorrection=1.00¦YCorrection=1.00¦PrintKind=0¦BorderSize=5000000¦LeftOffset=0¦BottomOffset=0¦Orientation=2¦PaperLength=1000¦PaperWidth=1000¦Scale=100¦PaperSource=15¦PrintQuality=600¦MediaType=1¦DitherType=10¦PaperKind=Letter¦PrintScaleMode=1
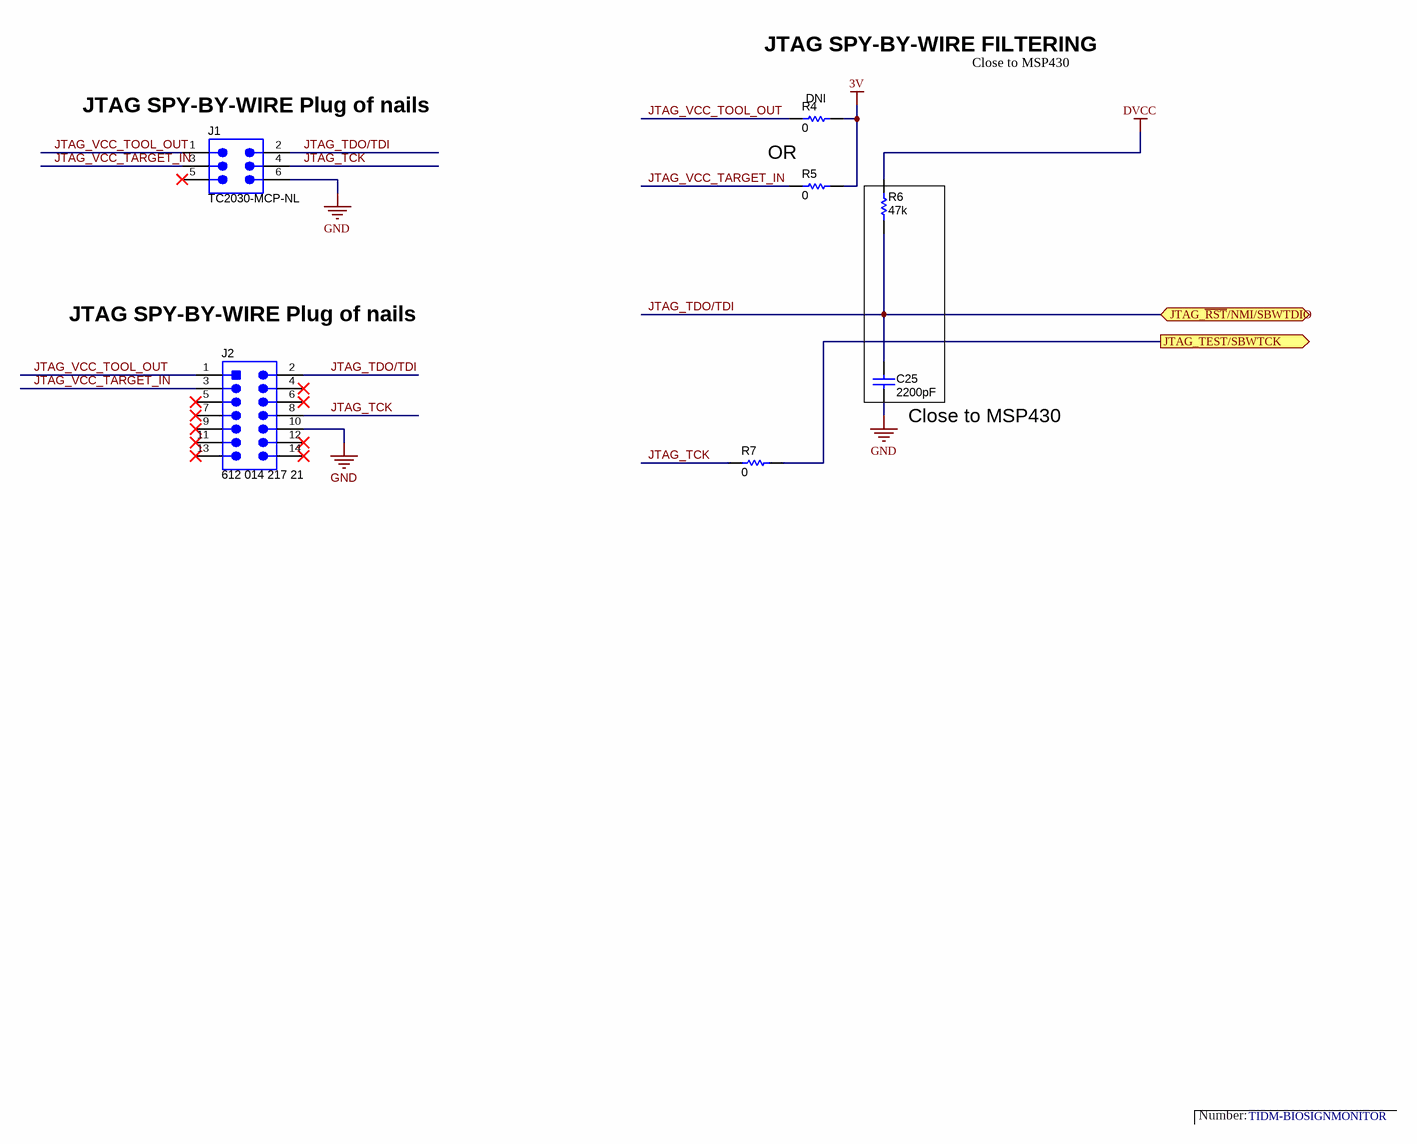
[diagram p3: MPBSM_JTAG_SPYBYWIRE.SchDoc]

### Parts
C25  ValueDisplayed: 2200pF  [0402]  (hidden comment: C1005X8R1H222K)
J1  TC2030-MCP-NL  [TC2030-MCP-NL]  (no BOM)
J2  612 014 217 21  [WURTH_612_014_217_21]
R4  ValueDisplayed: 0  [0402]  (hidden comment: ERJ-2GE0R00X)
R5  ValueDisplayed: 0  [0402]  (hidden comment: ERJ-2GE0R00X)
R6  ValueDisplayed: 47k  [0402]  (hidden comment: CRCW040247K0JNED)
R7  ValueDisplayed: 0  [0402]  (hidden comment: ERJ-2GE0R00X)

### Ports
JTAG_TEST/SBWTCK (out), JTAG_~{RST}/NMI/SBWTDIO (bidir)

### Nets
3V: R4.2 R5.2
DVCC: R6.2
GND: C25.2 J1.6 J2.10
JTAG_TCK: J1.4 J2.8 R7.1
JTAG_TDO/TDI: C25.1 J1.2 J2.2 R6.1 ; port JTAG_~{RST}/NMI/SBWTDIO
JTAG_TEST/SBWTCK: R7.2 ; port JTAG_TEST/SBWTCK
JTAG_VCC_TARGET_IN: J1.3 J2.3 R5.1
JTAG_VCC_TOOL_OUT: J1.1 J2.1 R4.1

Not connected (* = marked no-connect by the designer): J1 5*; J2 4* 5* 6* 7* 9* 11* 12* 13* 14*

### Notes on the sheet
- JTAG SPY-BY-WIRE FILTERING
- Close to MSP430
- (near J1) JTAG SPY-BY-WIRE Plug of nails
- OR
- (near R4) DNI
- (near J2) JTAG SPY-BY-WIRE Plug of nails
- (near C25) Close to MSP430
- Number:
- TIDM-BIOSIGNMONITOR

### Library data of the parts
C25 = C1005X8R1H222K: CAP, CERM, 2200 pF, 50 V, +/- 10%, X8R, 0402; Manufacturer: TDK; Polarized: N; CompType: Capacitor; Value: 2200pF; U/M: EA; Cap_F: 0.0000000022; Tolerance_%: 10; ESR_ohm: 0.1736; Value1: 0.1736 ohm; VDC_V: 50; Value2: 50V; TaMin_C: -55; TaMax_C: 150
J1 = TC2030-MCP-NL: Footprint for TC2030-MCP-NL; Manufacturer: Tag-Connect; SymbolCreator: a0799628; Note: Footprint only, to mate with Tag-Connect cable P/N TC2030-MCP-NL; CompType: Receptacle; U/M: EA
J2 = 612 014 217 21: Header (Shrouded), 2.54 mm, 7x2, Gold, R/A, TH; Manufacturer: Wurth Elektronik; SymbolCreator: a0412235
R4 R5 R7 = ERJ-2GE0R00X: RES, 0, 5%, 0.063 W, 0402; Manufacturer: Panasonic; CompType: Resistor; Value: 0; Value_Code: 0000; Tolerance_%: 5; Power_W: 0.063; Value2: 0.063W; VDC_V: 50; TempCo: 600 ppm/C; EIA_Code: E24; U/M: EA
R6 = CRCW040247K0JNED: RES, 47 k, 5%, 0.063 W, 0402; Manufacturer: Vishay-Dale; CompType: Resistor; Value: 47k; Res_ohm: 47000; Value_Code: 47k0; Tolerance_%: 5; Power_W: 0.063; Value2: 0.063W; VDC_V: 50; TempCo: 200 ppm/C; EIA_Code: E24; U/M: EA

## Sheet MPBSM_GSR.SchDoc: MPBSM GSR Subcircuit
size 431 x 279 mm; Date: Not shown in title block; ApprovedBy: Not shown in title block; CheckedBy: Not shown in title block; Author: Not shown in title block; CompanyName: Not shown in title block; Engineer: Not shown in title block; Organization: Not shown in title block; Address1: Not shown in title block; Address2: Not shown in title block; Address3: Not shown in title block; Address4: Not shown in title block; DocumentNumber: 9; Revision: Use project parameter SCH_Rev; SheetNumber: 8; SheetTotal: 12; PageSetup: Record=PageOptions¦CenterHorizontal=True¦CenterVertical=True¦PrintScale=1.00¦XCorrection=1.00¦YCorrection=1.00¦PrintKind=0¦BorderSize=5000000¦LeftOffset=0¦BottomOffset=0¦Orientation=2¦PaperLength=1000¦PaperWidth=1000¦Scale=100¦PaperSource=15¦PrintQuality=600¦MediaType=1¦DitherType=10¦PaperKind=Letter¦PrintScaleMode=1
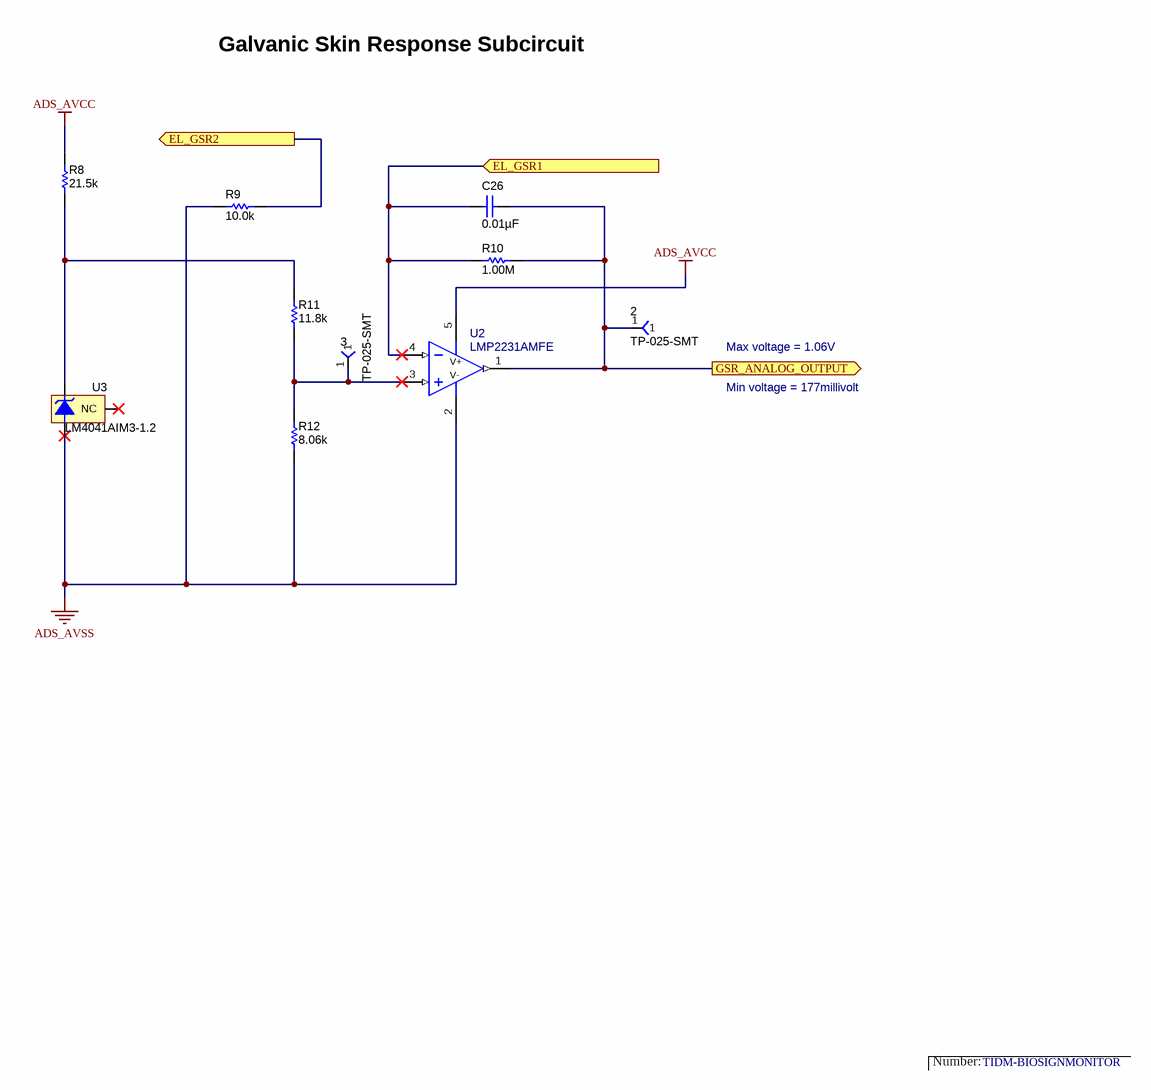
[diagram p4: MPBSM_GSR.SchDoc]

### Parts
2  TP-025-SMT  [TP_25MIL-SMT]
3  TP-025-SMT  [TP_25MIL-SMT]
C26  ValueDisplayed: 0.01µF  [0402]  (hidden comment: C1005X7R1E103K)
R8  ValueDisplayed: 21.5k  [0402]  (hidden comment: CRCW040221K5FKED)
R9  ValueDisplayed: 10.0k  [0402]  (hidden comment: CRCW040210K0FKED)
R10  ValueDisplayed: 1.00M  [0402]  (hidden comment: ERJ-2RKF1004X)
R11  ValueDisplayed: 11.8k  [0402]  (hidden comment: CRCW040211K8FKED)
R12  ValueDisplayed: 8.06k  [0402]  (hidden comment: CRCW04028K06FKED)
U2  LMP2231AMFE  [MF05A_L]
U3  LM4041AIM3-1.2  [MF03A_N]

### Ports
EL_GSR1 (in), EL_GSR2 (out), GSR_ANALOG_OUTPUT (out)

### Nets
ADS_AVCC: R8.2 U2.5(V+)
ADS_AVSS: R9.1 R12.1 U2.2(V-) U3.2(-V)
EL_GSR1: C26.2 R10.1 U2.4(IN-) ; port EL_GSR1
EL_GSR2: R9.2 ; port EL_GSR2
GSR_ANALOG_OUTPUT: 2.1 C26.1 R10.2 U2.1(OUT) ; port GSR_ANALOG_OUTPUT
Net3_1: 3.1 R11.1 R12.2 U2.3(IN+)
NetR8_1: R8.1 R11.2 U3.1(+V)

Not connected (* = marked no-connect by the designer): U3 3(NC)*

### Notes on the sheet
- Galvanic Skin Response Subcircuit
- Max voltage = 1.06V
- Min voltage = 177millivolt
- Number:
- TIDM-BIOSIGNMONITOR

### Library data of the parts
2 3 = TP-025-SMT: Test Point, O.025"; Manufacturer: STD; Value: STD
C26 = C1005X7R1E103K: CAP, CERM, 0.01 µF, 25 V, +/- 10%, X7R, 0402; Manufacturer: TDK; Polarized: N; CompType: Capacitor; Value: 0.01uF; U/M: EA; Cap_F: 0.00000001; Tolerance_%: 10; ESR_ohm: 0.0623; Value1: 0.0623 ohm; VDC_V: 25; Value2: 25V; TaMin_C: -55; TaMax_C: 125
R8 = CRCW040221K5FKED: RES, 21.5 k, 1%, 0.063 W, 0402; Manufacturer: Vishay-Dale; CompType: Resistor; Value: 21.5k; Res_ohm: 21500; Value_Code: 21k5; Tolerance_%: 1; Power_W: 0.063; Value2: 0.063W; VDC_V: 50; TempCo: 100 ppm/C; EIA_Code: E96; U/M: EA
R9 = CRCW040210K0FKED: RES, 10.0 k, 1%, 0.063 W, 0402; Manufacturer: Vishay-Dale; CompType: Resistor; Value: 10.0k; Res_ohm: 10000; Value_Code: 10k0; Tolerance_%: 1; Power_W: 0.063; Value2: 0.063W; VDC_V: 50; TempCo: 100 ppm/C; EIA_Code: E96; U/M: EA
R10 = ERJ-2RKF1004X: RES, 1.00 M, 1%, 0.1 W, 0402; Manufacturer: Panasonic; CompType: Resistor; Value: 1.00Meg; Res_ohm: 1000000; Value_Code: 1M00; Tolerance_%: 1; Power_W: 0.1; Value2: 0.1W; VDC_V: 50; TempCo: 100 ppm/C; EIA_Code: E96; U/M: EA
R11 = CRCW040211K8FKED: RES, 11.8 k, 1%, 0.063 W, 0402; Manufacturer: Vishay-Dale; CompType: Resistor; Value: 11.8k; Res_ohm: 11800; Value_Code: 11k8; Tolerance_%: 1; Power_W: 0.063; Value2: 0.063W; VDC_V: 50; TempCo: 100 ppm/C; EIA_Code: E96; U/M: EA
R12 = CRCW04028K06FKED: RES, 8.06 k, 1%, 0.063 W, 0402; Manufacturer: Vishay-Dale; CompType: Resistor; Value: 8.06k; Res_ohm: 8060; Value_Code: 8k06; Tolerance_%: 1; Power_W: 0.063; Value2: 0.063W; VDC_V: 50; TempCo: 100 ppm/C; EIA_Code: E96; U/M: EA
U2 = LMP2231AMFE: Single Micropower Precision Op Amp; Manufacturer: National Semiconductor; Characteristics: LMP2231AMFE Single Micropower Precision Op Amp; CompType: IC; Value: Analog; TaMin_C: -40 °C; TaMax_C: 125 °C; PowerWise: N; InputBiasCurrent: 0.02 pA; InputOffsetVoltage: 10 µV; SupplyCurrent: 10 µA; VoltageSupplyMax_V: 5.5 V; VoltageSupplyMin_V: 1.6 V; OutputType: Rail-to-Rail; SlewRate: 0.058 V/µs; GainBandwidthProduct: 130 kHz; Value1: 1.6 V - 5.5 V
U3 = LM4041AIM3-1.2: Precision Micropower Shunt Voltage Reference, 3-pin SOT-23; Manufacturer: Texas Instruments; PackageTopMarking: R1A*XTT; PowerWise: N; CompType: IC; SupplyVoltageMax_V: Not Applicable; SupplyCurrent: 12 mA; SymbolCreator: a0272897; TaMax_C: 85°C; TaMin_C: -40°C; Value: Analog

## Sheet MPBSM_Battery.SchDoc: Battery Subcircuit
size A3; Date: Not shown in title block; ApprovedBy: Not shown in title block; CheckedBy: Not shown in title block; Author: Not shown in title block; CompanyName: Not shown in title block; DrawnBy: Not shown in title block; Engineer: Not shown in title block; Organization: Not shown in title block; Address1: Not shown in title block; Address2: Not shown in title block; Address3: Not shown in title block; Address4: Not shown in title block; DocumentNumber: 3; Revision: Use project parameter SCH_Rev; SheetNumber: 3; SheetTotal: 12; PageSetup: Record=PageOptions¦CenterHorizontal=True¦CenterVertical=True¦PrintScale=0.69¦XCorrection=1.00¦YCorrection=1.00¦PrintKind=0¦BorderSize=5000000¦LeftOffset=0¦BottomOffset=0¦Orientation=2¦PaperLength=1000¦PaperWidth=1000¦Scale=100¦PaperSource=15¦PrintQuality=600¦MediaType=1¦DitherType=10¦PaperKind=Letter¦PrintScaleMode=1
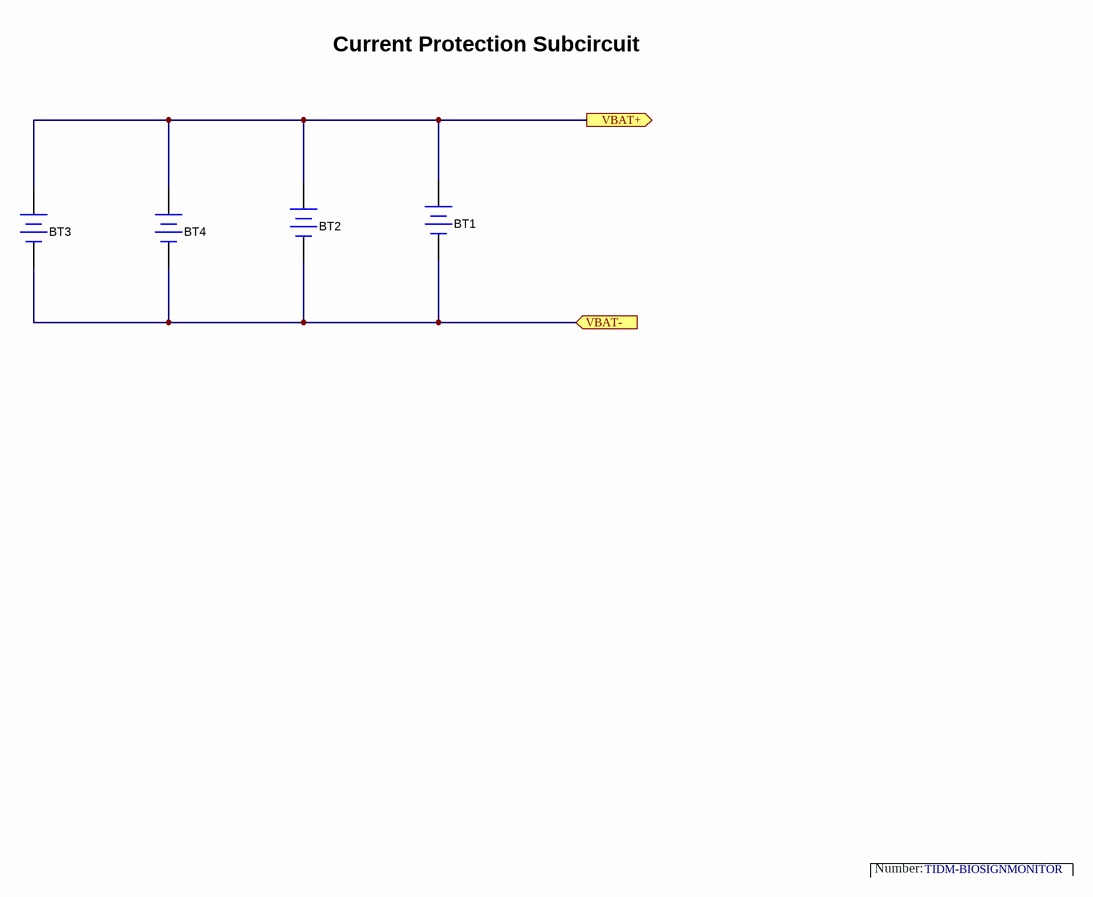
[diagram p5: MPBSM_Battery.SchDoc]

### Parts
BT1  XXXXXX  [Flat_Battery]  (value not drawn)
BT2  XXXXXX  [Flat_Battery]  (value not drawn)
BT3  2462  [Keystone_2462]  (value not drawn)
BT4  2462  [Keystone_2462]  (value not drawn)

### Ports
VBAT+ (out), VBAT- (in)

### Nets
GND: BT1.2(-) BT2.2(-) BT3.2(-) BT4.2(-) ; port VBAT-
BOOST_INPUT: BT1.1(+) BT2.1(+) BT3.1(+) BT4.1(+) ; port VBAT+

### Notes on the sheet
- Current Protection Subcircuit
- Number:
- TIDM-BIOSIGNMONITOR

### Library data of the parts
BT1 = Battery: Battery, Lithium Polymer, 3V, 25mAh; Manufacturer: Solicore; U/M: EA; Value: 3 Volts; TaMax_C: 60° C; TaMin_C: -10° C; Value1: 10mAh to 28mAh; Value2: Ultra-thin: 0.37mm – 0.45mm; SymbolCreator: a0272897
BT2 = Battery: Battery, Lithium Polymer, 3V, 25mAh; Manufacturer: Solicore; U/M: EA; Value: 3 Volts; Capacity: 10mAh to 28mAh; TaMax_C: 60° C; TaMin_C: -10° C; Value2: Ultra-thin: 0.37mm – 0.45mm; SymbolCreator: a0272897
BT3 BT4 = 2462: 2x AA Battery Holder, Through-hole mount; Manufacturer: Keystone

## Sheet MPBSM_BoostConverter.SchDoc: Boost Converter Subcircuit
size A3; Date: Not shown in title block; ApprovedBy: Not shown in title block; CheckedBy: Not shown in title block; Author: Not shown in title block; CompanyName: Not shown in title block; DrawnBy: Not shown in title block; Engineer: Not shown in title block; Organization: Not shown in title block; Address1: Not shown in title block; Address2: Not shown in title block; Address3: Not shown in title block; Address4: Not shown in title block; DocumentNumber: 4; Revision: Use project parameter SCH_Rev; SheetNumber: 4; SheetTotal: 12; PageSetup: Record=PageOptions¦CenterHorizontal=True¦CenterVertical=True¦PrintScale=0.69¦XCorrection=1.00¦YCorrection=1.00¦PrintKind=0¦BorderSize=5000000¦LeftOffset=0¦BottomOffset=0¦Orientation=2¦PaperLength=1000¦PaperWidth=1000¦Scale=100¦PaperSource=15¦PrintQuality=600¦MediaType=1¦DitherType=10¦PaperKind=Letter¦PrintScaleMode=1
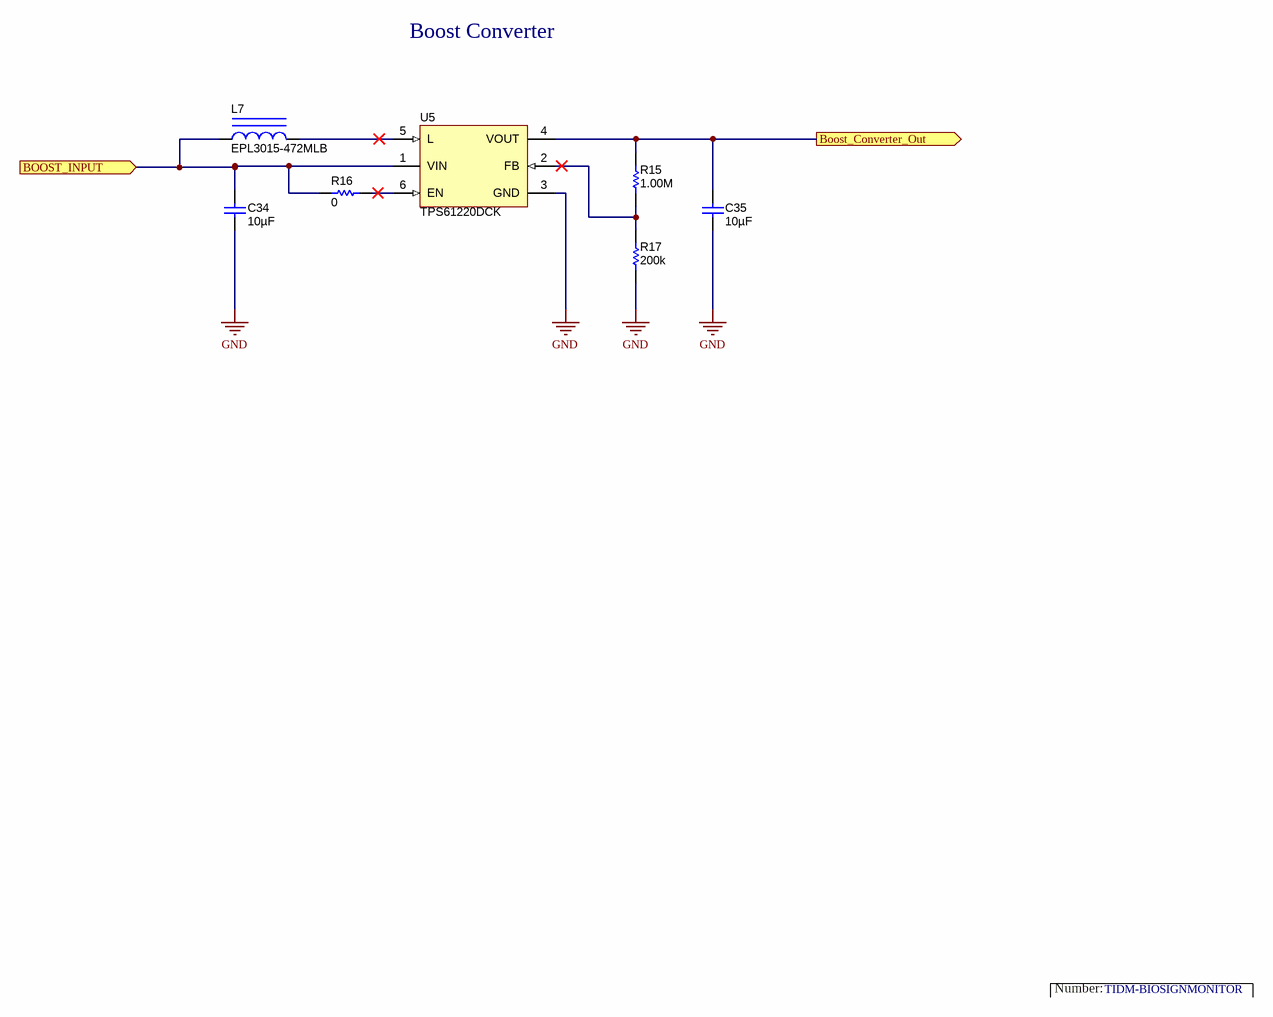
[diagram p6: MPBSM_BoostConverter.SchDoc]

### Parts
C34  ValueDisplayed: 10µF  [0402]  (hidden comment: CL05A106MQ5NUNC)
C35  ValueDisplayed: 10µF  [0402]  (hidden comment: CL05A106MQ5NUNC)
L7  EPL3015-472MLB  [EPL3015]
R15  ValueDisplayed: 1.00M  [0402]  (hidden comment: ERJ-2RKF1004X)
R16  ValueDisplayed: 0  [0402]  (hidden comment: ERJ-2GE0R00X)
R17  ValueDisplayed: 200k  [0402]  (hidden comment: ERJ-2RKF2003X)
U5  TPS61220DCK  [DCK0006A_N]

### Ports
Boost_Converter_Out (out), BOOST_INPUT (in)

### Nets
3V: C35.1 R15.2 U5.4(VOUT) ; port Boost_Converter_Out
GND: C34.2 C35.2 R17.1 U5.3(GND)
BOOST_INPUT: C34.1 L7.1 R16.1 U5.1(VIN) ; port BOOST_INPUT
NetL7_2: L7.2 U5.5(L)
NetR15_1: R15.1 R17.2 U5.2(FB)
NetR16_2: R16.2 U5.6(EN)

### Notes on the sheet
- Boost Converter
- Number:
- TIDM-BIOSIGNMONITOR

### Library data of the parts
C34 C35 = CL05A106MQ5NUNC: CAP, CERM, 10 µF, 6.3 V, +/- 20%, X5R, 0402; Manufacturer: Samsung; Polarized: N; CompType: Capacitor; Value: 10uF; U/M: EA; Cap_F: 0.00001; Tolerance_%: 20; Value1: Unknown; VDC_V: 6.3; Value2: 6.3V; TaMin_C: -55; TaMax_C: 85
L7 = EPL3015-472MLB: Inductor, Shielded, Ferrite, 4.7uH, 1.2A, 0.14 ohm, SMD; Manufacturer: Coilcraft; Ind_H: 4.7E-6; ValueDisplayed: 4.7µH; Imax_A: 1.2; Irms: 1.4A @ 40C rise; Isat: 1.2A @ 30% inductance drop; DCR_ohm: 0.14
R15 = ERJ-2RKF1004X: as R10 on sheet MPBSM_GSR
R16 = ERJ-2GE0R00X: as R4 on sheet MPBSM_JTAG_SPYBYWIRE
R17 = ERJ-2RKF2003X: RES, 200 k, 1%, 0.1 W, 0402; Manufacturer: Panasonic; CompType: Resistor; Value: 200k; Res_ohm: 200000; Tolerance_%: 1; Power_W: 0.1; Value2: 0.1W; VDC_V: 50; TempCo: 100 ppm/C; EIA_Code: E96; U/M: EA
U5 = TPS61220DCK: LOW INPUT VOLTAGE STEP-UP CONVERTER IN 6 PIN SC-70 PACKAGE, DCK0006A; Manufacturer: Texas Instruments; SymbolCreator: a0799628; CompType: IC; U/M: EA; Value: Analog; Value1: 0.7 V to 5.5 V; Value2: 200 mA; TaMax_C: -40°C; TaMin_C: 125°C; InputVoltageMin_V: 0.7 V; InputVoltageMax_V: 5.5 V; SwitchingFrequency: 2 MHz

## Sheet MPBSM_NFC_Trans.SchDoc: NFC Transponder Subcircuit
size A3; Date: Not shown in title block; ApprovedBy: Not shown in title block; CheckedBy: Not shown in title block; Author: Not shown in title block; CompanyName: Not shown in title block; DrawnBy: Not shown in title block; Engineer: Not shown in title block; Organization: Not shown in title block; Address1: Not shown in title block; Address2: Not shown in title block; Address3: Not shown in title block; Address4: Not shown in title block; DocumentNumber: 7; Revision: Use project parameter SCH_Rev; SheetNumber: 9; SheetTotal: 12; PageSetup: Record=PageOptions¦CenterHorizontal=True¦CenterVertical=True¦PrintScale=0.69¦XCorrection=1.00¦YCorrection=1.00¦PrintKind=0¦BorderSize=5000000¦LeftOffset=0¦BottomOffset=0¦Orientation=2¦PaperLength=1000¦PaperWidth=1000¦Scale=100¦PaperSource=15¦PrintQuality=600¦MediaType=1¦DitherType=10¦PaperKind=Letter¦PrintScaleMode=1
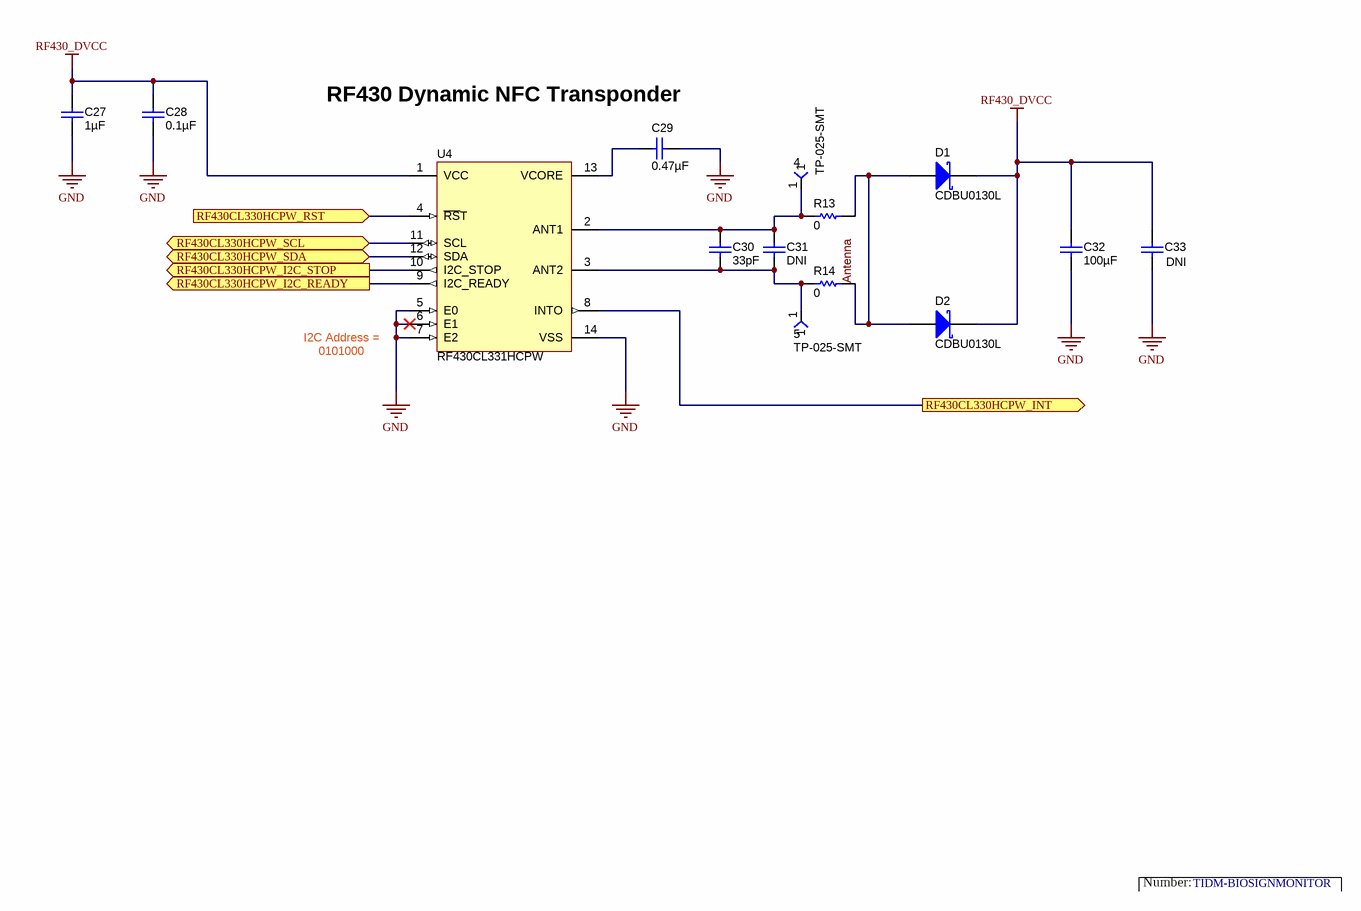
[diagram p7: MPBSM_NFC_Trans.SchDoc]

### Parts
4  TP-025-SMT  [TP_25MIL-SMT]
5  TP-025-SMT  [TP_25MIL-SMT]
C27  ValueDisplayed: 1µF  [0402]  (hidden comment: C1005X5R0J105M)
C28  ValueDisplayed: 0.1µF  [0402]  (hidden comment: C1005X5R1A104K)
C29  ValueDisplayed: 0.47µF  [0402]  (hidden comment: GRM155R60J474KE19D)
C30  ValueDisplayed: 33pF  [0603]  (hidden comment: C1608C0G1H330J)
C31  GRM1555C1H390JA01D  [0402]  (value not drawn)
C32  ValueDisplayed: 100µF  [1206_190]  (hidden comment: C3216X5R1A107M160AC)
C33  Used in BOM report  [0603]  (value not drawn)
D1  CDBU0130L  [SOD-523F]
D2  CDBU0130L  [SOD-523F]
R13  ValueDisplayed: 0  [0402]  (hidden comment: ERJ-2GE0R00X)
R14  ValueDisplayed: 0  [0402]  (hidden comment: ERJ-2GE0R00X)
U4  RF430CL331HCPW  [PW0014A_M]

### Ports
RF430CL330HCPW_I2C_READY (out), RF430CL330HCPW_I2C_STOP (out), RF430CL330HCPW_INT (out), RF430CL330HCPW_RST (in), RF430CL330HCPW_SCL (bidir), RF430CL330HCPW_SDA (bidir)

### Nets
GND: C27.2 C28.2 C29.1 C32.2 C33.2 U4.5(E0) U4.6(E1) U4.7(E2) U4.14(VSS)
RF430_DVCC: C27.1 C28.1 C32.1 C33.1 D1.1(K) D2.1(K) U4.1(VCC)
Antenna: D1.2(A) D2.2(A) R13.2 R14.2
MSP_P1.0_INT: U4.10(I2C_STOP) ; port RF430CL330HCPW_I2C_STOP
MSP_P4.0_INT: U4.9(I2C_READY) ; port RF430CL330HCPW_I2C_READY
MSP_P4.1_INT: U4.8(INTO) ; port RF430CL330HCPW_INT
MSP_P9.3_OUT: U4.4(~{RS}T) ; port RF430CL330HCPW_RST
MSP_UCB0SCL_TMP103_SCL_RF430CL330HCPW_SCL: U4.11(SCL) ; port RF430CL330HCPW_SCL
MSP_UCB0SDA_TMP103_SDA_RF430CL330HCPW_SDA: U4.12(SDA) ; port RF430CL330HCPW_SDA
Net4_1: 4.1 C30.1 C31.1 R13.1 U4.2(ANT1)
Net5_1: 5.1 C30.2 C31.2 R14.1 U4.3(ANT2)
NetC29_2: C29.2 U4.13(VCORE)

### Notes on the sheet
- (near C29) RF430 Dynamic NFC Transponder
- I2C Address =
- 0101000
- Number:
- TIDM-BIOSIGNMONITOR

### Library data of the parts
4 5 = TP-025-SMT: as 2 on sheet MPBSM_GSR
C27 = C1005X5R0J105M: CAP, CERM, 1 µF, 6.3 V, +/- 20%, X5R, 0402; Manufacturer: TDK; Polarized: N; CompType: Capacitor; Value: 1uF; U/M: EA; Cap_F: 0.000001; Tolerance_%: 20; ESR_ohm: 0.0079; Value1: 0.0079 ohm; VDC_V: 6.3; Value2: 6.3V; TaMin_C: -55; TaMax_C: 85
C28 = C1005X5R1A104K: CAP, CERM, 0.1 µF, 10 V, +/- 10%, X5R, 0402; Manufacturer: TDK; Polarized: N; CompType: Capacitor; Value: 0.1uF; U/M: EA; Cap_F: 0.0000001; Tolerance_%: 10; ESR_ohm: 0.0186; Value1: 0.0186 ohm; Value2: 10V; TaMin_C: -55; TaMax_C: 85
C29 = GRM155R60J474KE19D: CAP, CERM, 0.47 µF, 6.3 V, +/- 10%, X5R, 0402; Manufacturer: MuRata; Polarized: N; CompType: Capacitor; Value: 0.47uF; U/M: EA; Cap_F: 0.00000047; Tolerance_%: 10; Value1: Unknown; VDC_V: 6.3; Value2: 6.3V; TaMin_C: -55; TaMax_C: 85
C30 = C1608C0G1H330J: CAP, CERM, 33 pF, 50 V, +/- 5%, C0G/NP0, 0603; Manufacturer: TDK; Polarized: N; CompType: Capacitor; Value: 33pF; U/M: EA; Cap_F: 0.000000000033; Tolerance_%: 5; ESR_ohm: 0.2649; Value1: 0.2649 ohm; VDC_V: 50; Value2: 50V; TaMin_C: -55; TaMax_C: 125
C31 = GRM1555C1H390JA01D: CAP, CERM, 39pF, 50V, +/-5%, C0G/NP0, 0402; Manufacturer: MuRata; Polarized: N; CompType: Capacitor; U/M: EA; Cap_F: 0.000000000039; Tolerance_%: 5; Value1: Unknown; VDC_V: 50; TaMin_C: -55; TaMax_C: 125
C32 = C3216X5R1A107M160AC: CAP, CERM, 100 µF, 10 V, +/- 20%, X5R, 1206_190; Manufacturer: TDK; Polarized: N; CompType: Capacitor; Value: 100uF; U/M: EA; Cap_F: 0.0001; Tolerance_%: 20; Value1: Unknown; VDC_V: 10; Value2: 10V; TaMin_C: -55; TaMax_C: 85
C33 = Capacitor: CAP, CERM, xxxF, xxV, [TempCo], xx%, [PackageReference]; Polarized: N; Value: Not Applicable; U/M: EA
D1 D2 = CDBU0130L: Diode, Schottky, 35V, 0.1A, SOD-523F; Manufacturer: Comchip Technology; U/M: EA; Value2: V; Io_A: 0.1; Vr_V: 35; TJmax_C: 125
R13 R14 = ERJ-2GE0R00X: as R4 on sheet MPBSM_JTAG_SPYBYWIRE
U4 = RF430CL331H: The Texas Instruments Dynamic NFC Interface Transponder RF430CL331H is an NFC Tag Type 4 device  that combines a wireless NFC interface and a wired SPI or I2C interface to connect the device to a host.; Alternate PartNumber: RF430CL330HCPW; SymbolCreator: a0272897; CompType: IC; U/M: EA, IN, or GM; SupplyVoltageMax_V: 3.6V; SupplyVoltageMin_V: 2 V; SupplyVoltage: 2 V - 3.6 V; SupplyCurrent: 250 uA; TaMax_C: 85 °C; TaMin_C: -40 °C; Value: Mixed-Signal

## Sheet MPBSM_Temperature.SchDoc: MPBSM Temperature Subcircuit
size A3; Date: Not shown in title block; ApprovedBy: Not shown in title block; CheckedBy: Not shown in title block; Author: Not shown in title block; CompanyName: Not shown in title block; DrawnBy: Not shown in title block; Engineer: Not shown in title block; Organization: Not shown in title block; Address1: Not shown in title block; Address2: Not shown in title block; Address3: Not shown in title block; Address4: Not shown in title block; DocumentNumber: 11; Revision: Use project parameter SCH_Rev; SheetNumber: 11; SheetTotal: 12; PageSetup: Record=PageOptions¦CenterHorizontal=True¦CenterVertical=True¦PrintScale=0.69¦XCorrection=1.00¦YCorrection=1.00¦PrintKind=0¦BorderSize=5000000¦LeftOffset=0¦BottomOffset=0¦Orientation=2¦PaperLength=1000¦PaperWidth=1000¦Scale=100¦PaperSource=15¦PrintQuality=600¦MediaType=1¦DitherType=10¦PaperKind=Letter¦PrintScaleMode=1
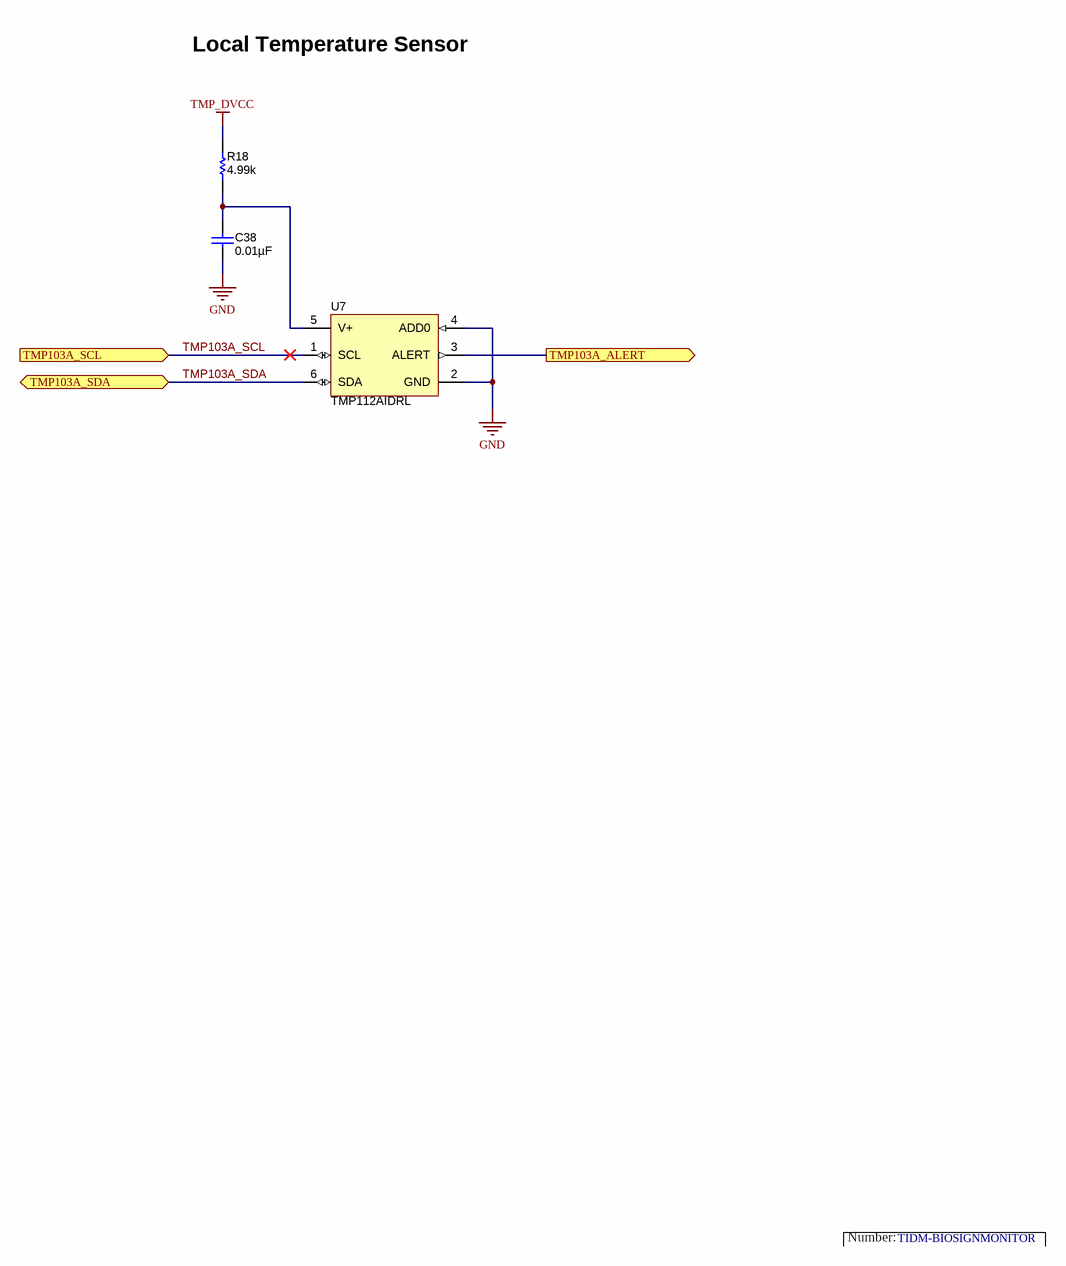
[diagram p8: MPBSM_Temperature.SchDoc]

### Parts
C38  ValueDisplayed: 0.01µF  [0402]  (hidden comment: C1005X7R1E103K)
R18  ValueDisplayed: 4.99k  [0402]  (hidden comment: CRCW04024K99FKED)
U7  TMP112AIDRL  [DRL0006A]

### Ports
TMP103A_ALERT (out), TMP103A_SCL (in), TMP103A_SDA (bidir)

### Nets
GND: C38.2 U7.2(GND) U7.4(ADD0)
TMP_DVCC: R18.2
MSP_P2.6_INT: U7.3(ALERT) ; port TMP103A_ALERT
TMP103A_SCL: U7.1(SCL) ; port TMP103A_SCL  [project net MSP_UCB0SCL_TMP103_SCL_RF430CL330HCPW_SCL]
TMP103A_SDA: U7.6(SDA) ; port TMP103A_SDA  [project net MSP_UCB0SDA_TMP103_SDA_RF430CL330HCPW_SDA]
NetC38_1: C38.1 R18.1 U7.5(V+)

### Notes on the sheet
- Local Temperature Sensor
- Number:
- TIDM-BIOSIGNMONITOR

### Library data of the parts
C38 = C1005X7R1E103K: as C26 on sheet MPBSM_GSR
R18 = CRCW04024K99FKED: RES, 4.99 k, 1%, 0.063 W, 0402; Manufacturer: Vishay-Dale; CompType: Resistor; Value: 4.99k; Res_ohm: 4990; Value_Code: 4k99; Tolerance_%: 1; Power_W: 0.063; Value2: 0.063W; VDC_V: 50; TempCo: 100 ppm/C; EIA_Code: E96; U/M: EA
U7 = TMP112AIDRL: High-Accuracy, Low-Power, Digital Temperature Sensor With SMBus(TM)/Two-Wire Serial Interface, DRL0006A; Manufacturer: Texas Instruments; SymbolCreator: a0799628; CompType: IC; U/M: EA; SupplyCurrent: 10 uA; SupplyVoltage: 1.4 V - 3.6 V; SupplyVoltageMax_V: 3.6 V; SupplyVoltageMin_V: 1.4 V; TaMax_C: + 125 °C; TaMin_C: - 40 °C; Value: Mixed-Signal

## Sheet MPBSM_ECG.SchDoc: MPBSM ECG subcircuit
size 431 x 279 mm; Date: Not shown in title block; ApprovedBy: Not shown in title block; CheckedBy: Not shown in title block; Author: Not shown in title block; CompanyName: Not shown in title block; Engineer: Not shown in title block; Organization: Not shown in title block; Address1: Not shown in title block; Address2: Not shown in title block; Address3: Not shown in title block; Address4: Not shown in title block; DocumentNumber: 8; Revision: Use project parameter SCH_Rev; SheetNumber: 7; SheetTotal: 12; PageSetup: Record=PageOptions¦CenterHorizontal=True¦CenterVertical=True¦PrintScale=1.00¦XCorrection=1.00¦YCorrection=1.00¦PrintKind=0¦BorderSize=5000000¦LeftOffset=0¦BottomOffset=0¦Orientation=2¦PaperLength=1000¦PaperWidth=1000¦Scale=100¦PaperSource=15¦PrintQuality=600¦MediaType=1¦DitherType=10¦PaperKind=Letter¦PrintScaleMode=1
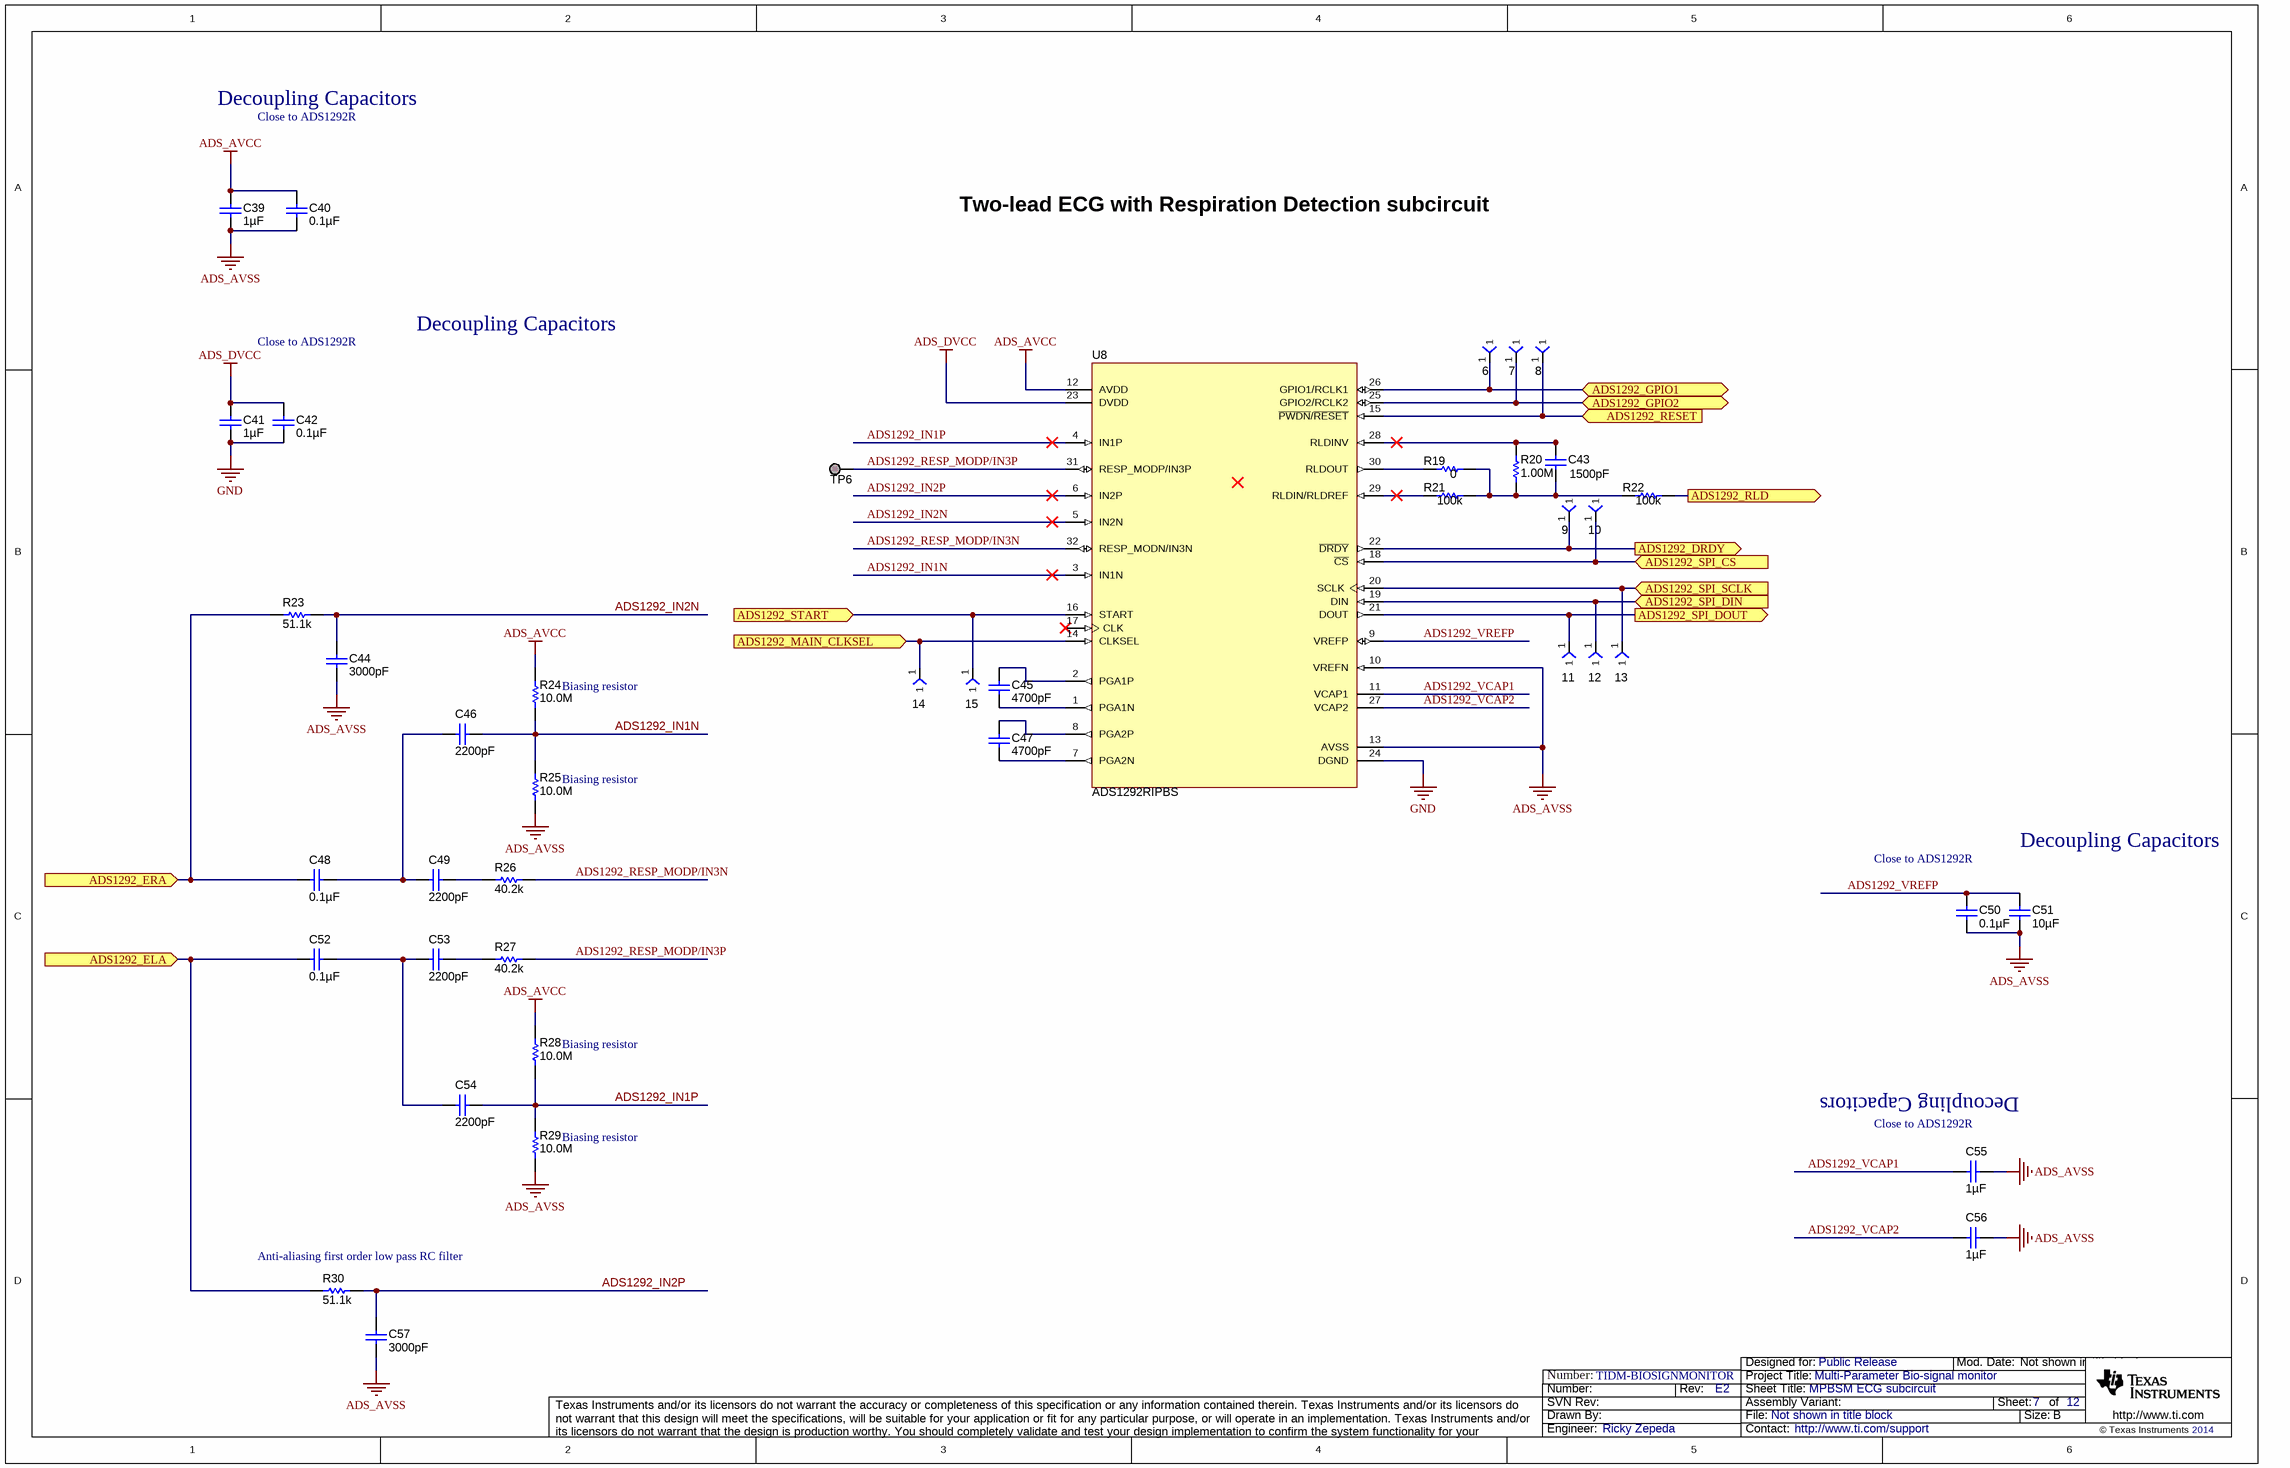
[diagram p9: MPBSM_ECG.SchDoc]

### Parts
6  TP-025-SMT  [TP_25MIL-SMT]  (value not drawn)
7  TP-025-SMT  [TP_25MIL-SMT]  (value not drawn)
8  TP-025-SMT  [TP_25MIL-SMT]  (value not drawn)
9  TP-025-SMT  [TP_25MIL-SMT]  (value not drawn)
10  TP-025-SMT  [TP_25MIL-SMT]  (value not drawn)
11  TP-025-SMT  [TP_25MIL-SMT]  (value not drawn)
12  TP-025-SMT  [TP_25MIL-SMT]  (value not drawn)
13  TP-025-SMT  [TP_25MIL-SMT]  (value not drawn)
14  TP-025-SMT  [TP_25MIL-SMT]  (value not drawn)
15  TP-025-SMT  [TP_25MIL-SMT]  (value not drawn)
C39  ValueDisplayed: 1µF  [0402]  (hidden comment: C1005X5R1C105K050BC)
C40  ValueDisplayed: 0.1µF  [0402]  (hidden comment: C1005X5R1A104K)
C41  ValueDisplayed: 1µF  [0402]  (hidden comment: C1005X5R1C105K050BC)
C42  ValueDisplayed: 0.1µF  [0402]  (hidden comment: C1005X5R1A104K)
C43  ValueDisplayed: 1500pF  [0603]  (hidden comment: C0603C152K5RACTU)
C44  ValueDisplayed: 3000pF  [0603]  (hidden comment: GRM1885C1H302JA01D)
C45  ValueDisplayed: 4700pF  [0402]  (hidden comment: GRM155R61A472KA01D)
C46  ValueDisplayed: 2200pF  [0402]  (hidden comment: C1005X8R1H222K)
C47  ValueDisplayed: 4700pF  [0402]  (hidden comment: GRM155R61A472KA01D)
C48  ValueDisplayed: 0.1µF  [0402]  (hidden comment: C1005X5R1A104K)
C49  ValueDisplayed: 2200pF  [0402]  (hidden comment: C1005X8R1H222K)
C50  ValueDisplayed: 0.1µF  [0402]  (hidden comment: C1005X5R1A104K)
C51  ValueDisplayed: 10µF  [0603]  (hidden comment: C1608X5R0J106M)
C52  ValueDisplayed: 0.1µF  [0402]  (hidden comment: C1005X5R1A104K)
C53  ValueDisplayed: 2200pF  [0402]  (hidden comment: C1005X8R1H222K)
C54  ValueDisplayed: 2200pF  [0402]  (hidden comment: C1005X8R1H222K)
C55  ValueDisplayed: 1µF  [0402]  (hidden comment: C1005X5R1C105K050BC)
C56  ValueDisplayed: 1µF  [0402]  (hidden comment: C1005X5R1C105K050BC)
C57  ValueDisplayed: 3000pF  [0603]  (hidden comment: GRM1885C1H302JA01D)
R19  ValueDisplayed: 0  [0402]  (hidden comment: ERJ-2GE0R00X)
R20  ValueDisplayed: 1.00M  [0402]  (hidden comment: ERJ-2RKF1004X)
R21  ValueDisplayed: 100k  [0402]  (hidden comment: ERJ-2RKF1003X)
R22  ValueDisplayed: 100k  [0402]  (hidden comment: ERJ-2RKF1003X)
R23  ValueDisplayed: 51.1k  [0402]  (hidden comment: CRCW040251K1FKED)
R24  ValueDisplayed: 10.0M  [0402]  (hidden comment: CRCW040210M0FKED)
R25  ValueDisplayed: 10.0M  [0402]  (hidden comment: CRCW040210M0FKED)
R26  ValueDisplayed: 40.2k  [0402]  (hidden comment: CRCW040240K2FKED)
R27  ValueDisplayed: 40.2k  [0402]  (hidden comment: CRCW040240K2FKED)
R28  ValueDisplayed: 10.0M  [0402]  (hidden comment: CRCW040210M0FKED)
R29  ValueDisplayed: 10.0M  [0402]  (hidden comment: CRCW040210M0FKED)
R30  ValueDisplayed: 51.1k  [0402]  (hidden comment: CRCW040251K1FKED)
TP6  Pogo Pad  [PogoPad]  (value not drawn)  (no BOM)
U8  ADS1292RIPBS  [PBS0032A_N]

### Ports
ADS1292_DRDY (out), ADS1292_ELA (in), ADS1292_ERA (in), ADS1292_GPIO1 (bidir), ADS1292_GPIO2 (bidir), ADS1292_MAIN_CLKSEL (in), ADS1292_RESET (in), ADS1292_RLD (out), ADS1292_SPI_CS (in), ADS1292_SPI_DIN (in), ADS1292_SPI_DOUT (out), ADS1292_SPI_SCLK (in), ADS1292_START (in)

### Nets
ADS_AVCC: C39.1 C40.1 R24.2 R28.2 U8.12(AVDD)
ADS_AVSS: C39.2 C40.2 C44.2 C50.2 C51.2 C55.2 C56.2 C57.2 R25.1 R29.1 U8.10(VREFN) U8.13(AVSS)
ADS_DVCC: C41.1 C42.1 U8.23(DVDD)
GND: C41.2 C42.2 U8.24(DGND)
ADS1292_DRDY: 9.1 U8.22(~{DRDY}) ; port ADS1292_DRDY
ADS1292_ELA: C52.1 R30.1 ; port ADS1292_ELA
ADS1292_ERA: C48.1 R23.1 ; port ADS1292_ERA
ADS1292_GPIO1: 6.1 U8.26(GPIO1/RCLK1) ; port ADS1292_GPIO1
ADS1292_GPIO2: 7.1 U8.25(GPIO2/RCLK2) ; port ADS1292_GPIO2
ADS1292_IN1N: C46.1 R24.1 R25.2 U8.3(IN1N)
ADS1292_IN1P: C54.1 R28.1 R29.2 U8.4(IN1P)
ADS1292_IN2N: C44.1 R23.2 U8.5(IN2N)
ADS1292_IN2P: C57.1 R30.2 U8.6(IN2P)
ADS1292_MAIN_CLKSEL: 14.1 U8.14(CLKSEL) ; port ADS1292_MAIN_CLKSEL
ADS1292_RESET: 8.1 U8.15(~{PWDN}/~{RESET}) ; port ADS1292_RESET
ADS1292_RESP_MODP/IN3N: R26.2 U8.32(RESP_MODN/IN3N)
ADS1292_RESP_MODP/IN3P: R27.2 TP6.1 U8.31(RESP_MODP/IN3P)
ADS1292_RLD: R22.2 ; port ADS1292_RLD
ADS1292_SPI_CS: 10.1 U8.18(~{CS}) ; port ADS1292_SPI_CS
ADS1292_SPI_DIN: 12.1 U8.19(DIN) ; port ADS1292_SPI_DIN
ADS1292_SPI_DOUT: 11.1 U8.21(DOUT) ; port ADS1292_SPI_DOUT
ADS1292_SPI_SCLK: 13.1 U8.20(SCLK) ; port ADS1292_SPI_SCLK
ADS1292_START: 15.1 U8.16(START) ; port ADS1292_START
ADS1292_VCAP1: C55.1 U8.11(VCAP1)
ADS1292_VCAP2: C56.1 U8.27(VCAP2)
ADS1292_VREFP: C50.1 C51.1 U8.9(VREFP)
NetC43_1: C43.1 R19.2 R20.2 R21.2 R22.1
NetC43_2: C43.2 R20.1 U8.28(RLDINV)
NetC45_1: C45.1 U8.2(PGA1P)
NetC45_2: C45.2 U8.1(PGA1N)
NetC46_2: C46.2 C48.2 C49.2
NetC47_1: C47.1 U8.8(PGA2P)
NetC47_2: C47.2 U8.7(PGA2N)
NetC49_1: C49.1 R26.1
NetC52_2: C52.2 C53.2 C54.2
NetC53_1: C53.1 R27.1
NetR19_1: R19.1 U8.30(RLDOUT)
NetR21_1: R21.1 U8.29(RLDIN/RLDREF)

Not connected (* = marked no-connect by the designer): U8 17(CLK)*

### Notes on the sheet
- Decoupling Capacitors
- Close to ADS1292R
- Two-lead ECG with Respiration Detection subcircuit
- (near R24) Biasing resistor
- (near R25) Biasing resistor
- (near R28) Biasing resistor
- (near R29) Biasing resistor
- (near C55) Close to ADS1292R
- (near R30) Anti-aliasing first order low pass RC filter
- Number:
- TIDM-BIOSIGNMONITOR

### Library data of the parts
6-15 = TP-025-SMT: as 2 on sheet MPBSM_GSR
C39 C41 C55 C56 = C1005X5R1C105K050BC: CAP, CERM, 1 µF, 16 V, +/- 10%, X5R, 0402; Manufacturer: TDK; Polarized: N; CompType: Capacitor; Value: 1uF; U/M: EA; Cap_F: 0.000001; Tolerance_%: 10; Value1: Unknown; VDC_V: 16; Value2: 16V; TaMin_C: -55; TaMax_C: 85
C40 C42 C48 C50 C52 = C1005X5R1A104K: as C28 on sheet MPBSM_NFC_Trans
C43 = C0603C152K5RACTU: CAP, CERM, 1500 pF, 50 V, +/- 10%, X7R, 0603; Manufacturer: Kemet; Polarized: N; CompType: Capacitor; Value: 1500pF; U/M: EA; Cap_F: 0.0000000015; Tolerance_%: 10; Value1: Unknown; VDC_V: 50; Value2: 50V; TaMin_C: -55; TaMax_C: 125
C44 C57 = GRM1885C1H302JA01D: CAP, CERM, 3000 pF, 50 V, +/- 5%, C0G/NP0, 0603; Manufacturer: MuRata; Polarized: N; CompType: Capacitor; Value: 3000pF; U/M: EA; Cap_F: 0.000000003; Tolerance_%: 5; Value1: Unknown; VDC_V: 50; Value2: 50V; TaMin_C: -55; TaMax_C: 125
C45 C47 = GRM155R61A472KA01D: CAP, CERM, 4700 pF, 10 V, +/- 10%, X5R, 0402; Manufacturer: MuRata; Polarized: N; CompType: Capacitor; Value: 4700pF; U/M: EA; Cap_F: 0.0000000047; Tolerance_%: 10; Value1: Unknown; Value2: 10V; TaMin_C: -55; TaMax_C: 85
C46 C49 C53 C54 = C1005X8R1H222K: as C25 on sheet MPBSM_JTAG_SPYBYWIRE
C51 = C1608X5R0J106M: CAP, CERM, 10 µF, 6.3 V, +/- 20%, X5R, 0603; Manufacturer: TDK; Polarized: N; CompType: Capacitor; Value: 10uF; U/M: EA; Cap_F: 0.00001; Tolerance_%: 20; ESR_ohm: 0.005; Value1: 0.005 ohm; VDC_V: 6.3; Value2: 6.3V; IRMS_A: 1.9; TaMin_C: -25; TaMax_C: 85
R19 = ERJ-2GE0R00X: as R4 on sheet MPBSM_JTAG_SPYBYWIRE
R20 = ERJ-2RKF1004X: as R10 on sheet MPBSM_GSR
R21 R22 = ERJ-2RKF1003X: RES, 100 k, 1%, 0.1 W, 0402; Manufacturer: Panasonic; CompType: Resistor; Value: 100k; Res_ohm: 100000; Tolerance_%: 1; Power_W: 0.1; Value2: 0.1W; VDC_V: 50; TempCo: 100 ppm/C; EIA_Code: E96; U/M: EA
R23 R30 = CRCW040251K1FKED: RES, 51.1 k, 1%, 0.063 W, 0402; Manufacturer: Vishay-Dale; CompType: Resistor; Value: 51.1k; Res_ohm: 51100; Value_Code: 51k1; Tolerance_%: 1; Power_W: 0.063; Value2: 0.063W; VDC_V: 50; TempCo: 100 ppm/C; EIA_Code: E96; U/M: EA
R24 R25 R28 R29 = CRCW040210M0FKED: RES, 10.0 M, 1%, 0.063 W, 0402; Manufacturer: Vishay-Dale; CompType: Resistor; Value: 10.0Meg; Res_ohm: 10000000; Value_Code: 10M0; Tolerance_%: 1; Power_W: 0.063; Value2: 0.063W; VDC_V: 50; TempCo: 100 ppm/C; EIA_Code: E96; U/M: EA
R26 R27 = CRCW040240K2FKED: RES, 40.2 k, 1%, 0.063 W, 0402; Manufacturer: Vishay-Dale; CompType: Resistor; Value: 40.2k; Res_ohm: 40200; Value_Code: 40k2; Tolerance_%: 1; Power_W: 0.063; Value2: 0.063W; VDC_V: 50; TempCo: 100 ppm/C; EIA_Code: E96; U/M: EA
TP6 = PogoPad: Pad for Pogo Pin Connector; SymbolCreator: codlsc
U8 = ADS1292RIPBS: Low-Power, 2-Channel, 24-Bit Analog Front-End for Biopotential Measurement, PBS0032A; Alternate Manufacturer: None; Manufacturer: Texas Instruments; SymbolCreator: Altium; CompType: IC; U/M: EA; SupplyCurrent: 740µW; SupplyVoltageAnalog: 2.7 V ~ 5.25 V; SupplyVoltageAnalogMax_V: 5.25 V; SupplyVoltageAnalogMin_V: 2.7 V; TaMax_C: + 85 °C; TaMin_C: -40 °C; Value: Mixed-Signal; Value1: Not Applicable; SupplyVoltageDigitalMax_V: 3.6 V; SupplyVoltageDigital: 1.7 V ~ 3.6 V; SupplyVoltageDigitalMin_V: 1.7 V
